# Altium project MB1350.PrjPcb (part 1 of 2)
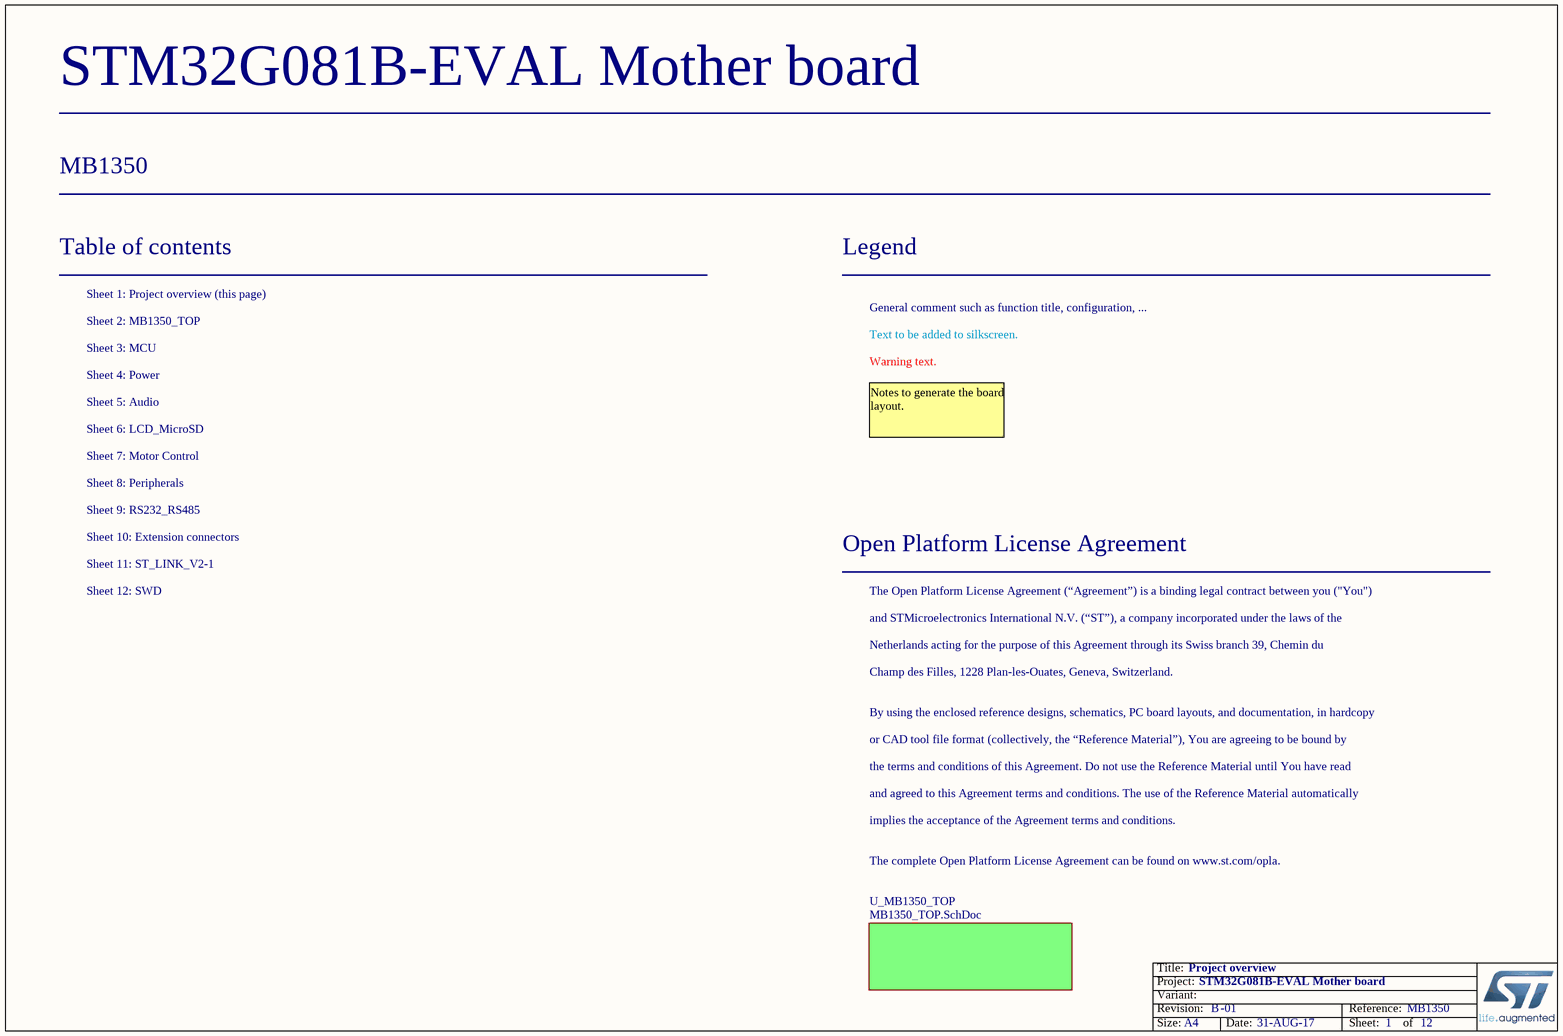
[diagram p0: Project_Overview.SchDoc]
Board_Assembly_Revision: 01; Board_Document_Date: 31-AUG-17; Board_Name: STM32G081B-EVAL Mother board; Board_PCB_Revision: B; Board_Reference: MB1350
12 sheets, 361 parts. Net scope: flat (ports and power ports of the same name join across sheets).
Sheets:
  Project_Overview.SchDoc
    U_MB1350_TOP = MB1350_TOP.SchDoc
      U_LCD_MicroSD = LCD_MicroSD.SchDoc
      U_RS232_RS485 = RS232_RS485.SchDoc
      U_ST_LINK_V2-1 = ST_LINK_V2-1.SchDoc
      U_SWD = SWD.SchDoc
      U_Peripherals = Peripherals.SchDoc
      U_MCU = MCU.SchDoc
      U_Power = Power.SchDoc
      U_Motor Control = Motor Control.SchDoc
      U_Extension connectors = Extension connectors.SchDoc
      U_Audio = Audio.SchDoc

## Sheet Project_Overview.SchDoc: Project overview
size A4; Date: Not used; ApprovedBy: Not used; CheckedBy: Not used; Author: Not used; CompanyName: STMicroelectronics; DrawnBy: Not used; Engineer: Not used; Organization: Not used; Address1: Not used; Address2: Not used; Address3: Not used; Address4: Not used; DocumentNumber: Not used; Revision: Not used; SheetNumber: 1; SheetTotal: 12

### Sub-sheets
U_MB1350_TOP = MB1350_TOP.SchDoc: no entries

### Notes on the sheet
- Table of contents
- Sheet 1: Project overview (this page)
- Legend
- General comment such as function title, configuration, ...
- Sheet 2: MB1350_TOP
- Sheet 3: MCU
- Sheet 4: Power
- Text to be added to silkscreen.
- Warning text.
- Sheet 6: LCD_MicroSD
- Sheet 5: Audio
- Notes to generate the board layout.
- Sheet 7: Motor Control
- Sheet 9: RS232_RS485
- Sheet 8: Peripherals
- Sheet 10: Extension connectors
- Sheet 11: ST_LINK_V2-1
- Open Platform License Agreement
- Sheet 12: SWD
- The Open Platform License Agreement (“Agreement”) is a binding legal contract between you ("You")
- and STMicroelectronics International N.V. (“ST”), a company incorporated under the laws of the
- Netherlands acting for the purpose of this Agreement through its Swiss branch 39, Chemin du
- Champ des Filles, 1228 Plan-les-Ouates, Geneva, Switzerland.
- By using the enclosed reference designs, schematics, PC board layouts, and documentation, in hardcopy
- or CAD tool file format (collectively, the “Reference Material”), You are agreeing to be bound by
- the terms and conditions of this Agreement. Do not use the Reference Material until You have read
- and agreed to this Agreement terms and conditions. The use of the Reference Material automatically
- implies the acceptance of the Agreement terms and conditions.
- The complete Open Platform License Agreement can be found on www.st.com/opla.

## Sheet MB1350_TOP.SchDoc: MB1350_TOP
size A4; SheetNumber: 2; SheetTotal: 12
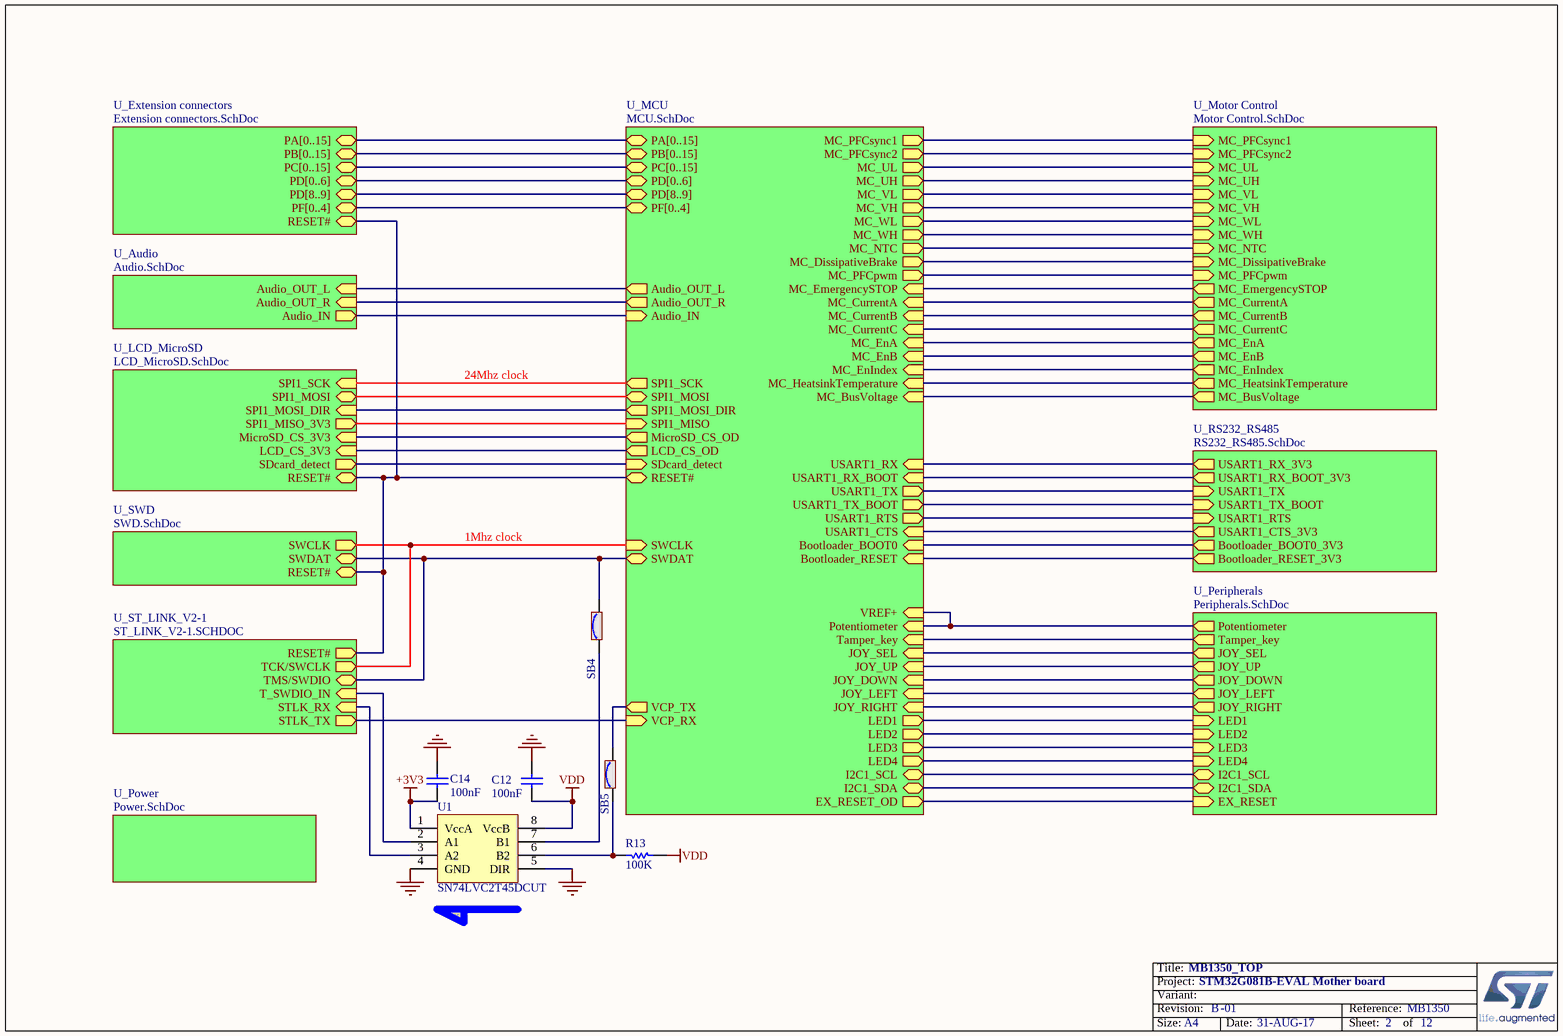
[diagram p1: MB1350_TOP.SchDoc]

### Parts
C12  100nF  [0603C]
C14  100nF  [0603C]
R13  100K  [0603R]
SB4  Solder Bridge ON  [SB_0603]  (value not drawn)
SB5  Solder Bridge ON  [SB_0603]  (value not drawn)
U1  SN74LVC2T45DCUT  [USOP8_0R5_2X3R1]

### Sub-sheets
U_Audio = Audio.SchDoc: Audio_IN (out), Audio_OUT_L (in), Audio_OUT_R (in)
U_Extension connectors = Extension connectors.SchDoc: PA[0..15] (bidir), PB[0..15] (bidir), PC[0..15] (bidir), PD[0..6] (bidir), PF[0..4] (bidir), PD[8..9] (bidir), RESET# (bidir)
U_LCD_MicroSD = LCD_MicroSD.SchDoc: MicroSD_CS_3V3 (in), LCD_CS_3V3 (in), SDcard_detect (out), RESET# (bidir), SPI1_MISO_3V3 (out), SPI1_MOSI (bidir), SPI1_MOSI_DIR (in), SPI1_SCK (in)
U_MCU = MCU.SchDoc: RESET# (bidir), LED4 (out), LED3 (out), LED1 (out), LED2 (out), Bootloader_BOOT0 (in), Bootloader_RESET (in), JOY_SEL (in), MC_BusVoltage (in), MC_CurrentA (in), Audio_OUT_L (out), Audio_OUT_R (out), SPI1_SCK (out), Potentiometer (in), SWCLK (in), USART1_TX_BOOT (out), MC_EnA (in), USART1_RX_BOOT (in), Audio_IN (in), SPI1_MOSI_DIR (out), MC_EnB (in), I2C1_SCL (bidir), I2C1_SDA (bidir), MC_EnIndex (in), MC_DissipativeBrake (out), MC_EmergencySTOP (in), SDcard_detect (in), MC_PFCsync1 (out), LCD_CS_OD (out), MicroSD_CS_OD (out), JOY_UP (in), JOY_DOWN (in), MC_HeatsinkTemperature (in), MC_CurrentC (in), MC_CurrentB (in), MC_PFCsync2 (out), MC_PFCpwm (out), Tamper_key (in), USART1_CTS (in), USART1_RTS (out), USART1_TX (out), USART1_RX (in), EX_RESET_OD (out), JOY_LEFT (in), JOY_RIGHT (in), MC_NTC (out), MC_UH (out), MC_UL (out), MC_WL (out), MC_VH (out), MC_VL (out), MC_WH (out), SPI1_MISO (in), SPI1_MOSI (bidir), SWDAT (bidir), VREF+ (in), PA[0..15] (bidir), PB[0..15] (bidir), PC[0..15] (bidir), PD[0..6] (bidir), PF[0..4] (bidir), PD[8..9] (bidir), VCP_TX (out), VCP_RX (in)
U_Motor Control = Motor Control.SchDoc: MC_EmergencySTOP (out), MC_CurrentA (out), MC_CurrentB (out), MC_CurrentC (out), MC_PFCsync1 (in), MC_PFCsync2 (in), MC_WL (in), MC_VH (in), MC_VL (in), MC_UH (in), MC_UL (in), MC_WH (in), MC_NTC (in), MC_DissipativeBrake (in), MC_PFCpwm (in), MC_EnA (out), MC_EnB (out), MC_HeatsinkTemperature (out), MC_BusVoltage (out), MC_EnIndex (out)
U_Peripherals = Peripherals.SchDoc: Potentiometer (out), LED4 (in), LED3 (in), LED1 (in), LED2 (in), Tamper_key (out), JOY_SEL (out), JOY_DOWN (out), JOY_LEFT (out), JOY_RIGHT (out), JOY_UP (out), EX_RESET (in), I2C1_SCL (bidir), I2C1_SDA (bidir)
U_Power = Power.SchDoc: no entries
U_RS232_RS485 = RS232_RS485.SchDoc: USART1_RX_3V3 (out), Bootloader_BOOT0_3V3 (out), Bootloader_RESET_3V3 (out), USART1_CTS_3V3 (out), USART1_RX_BOOT_3V3 (out), USART1_RTS (in), USART1_TX (in), USART1_TX_BOOT (in)
U_ST_LINK_V2-1 = ST_LINK_V2-1.SCHDOC: STLK_RX (in), STLK_TX (out), TMS/SWDIO (bidir), TCK/SWCLK (out), T_SWDIO_IN (in), RESET# (out)
U_SWD = SWD.SchDoc: RESET# (bidir), SWDAT (bidir), SWCLK (out)

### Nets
+3V3: C14.2 U1.1(VccA)
GND: C12.1 C14.1 U1.4(GND) U1.5(DIR)
VDD: C12.2 R13.2 U1.8(VccB)
NetR13_1: R13.1 SB5.1 U1.6(B2)
NetSB4_1: SB4.1 U1.7(B1)
NetSB4_2: SB4.2 ; sheet U_ST_LINK_V2-1/TMS/SWDIO, sheet U_SWD/SWDAT, sheet U_MCU/SWDAT
NetSB5_2: SB5.2 ; sheet U_MCU/VCP_TX
NetU1_2: U1.2(A1) ; sheet U_ST_LINK_V2-1/T_SWDIO_IN
NetU1_3: U1.3(A2) ; sheet U_ST_LINK_V2-1/STLK_RX
(unnamed): sheet U_LCD_MicroSD/MicroSD_CS_3V3, sheet U_MCU/MicroSD_CS_OD
(unnamed): sheet U_LCD_MicroSD/LCD_CS_3V3, sheet U_MCU/LCD_CS_OD  [a separate net that carries the same name]
(unnamed): sheet U_LCD_MicroSD/SDcard_detect, sheet U_MCU/SDcard_detect  [a separate net that carries the same name]
(unnamed): sheet U_LCD_MicroSD/RESET#, sheet U_ST_LINK_V2-1/RESET#, sheet U_SWD/RESET#, sheet U_MCU/RESET#, sheet U_Extension connectors/RESET#  [a separate net that carries the same name]
(unnamed): sheet U_LCD_MicroSD/SPI1_MISO_3V3, sheet U_MCU/SPI1_MISO  [a separate net that carries the same name]
(unnamed): sheet U_LCD_MicroSD/SPI1_MOSI, sheet U_MCU/SPI1_MOSI  [a separate net that carries the same name]
(unnamed): sheet U_LCD_MicroSD/SPI1_MOSI_DIR, sheet U_MCU/SPI1_MOSI_DIR  [a separate net that carries the same name]
(unnamed): sheet U_LCD_MicroSD/SPI1_SCK, sheet U_MCU/SPI1_SCK  [a separate net that carries the same name]
(unnamed): sheet U_RS232_RS485/USART1_RX_3V3, sheet U_MCU/USART1_RX  [a separate net that carries the same name]
(unnamed): sheet U_RS232_RS485/Bootloader_BOOT0_3V3, sheet U_MCU/Bootloader_BOOT0  [a separate net that carries the same name]
(unnamed): sheet U_RS232_RS485/Bootloader_RESET_3V3, sheet U_MCU/Bootloader_RESET  [a separate net that carries the same name]
(unnamed): sheet U_RS232_RS485/USART1_CTS_3V3, sheet U_MCU/USART1_CTS  [a separate net that carries the same name]
(unnamed): sheet U_RS232_RS485/USART1_RX_BOOT_3V3, sheet U_MCU/USART1_RX_BOOT  [a separate net that carries the same name]
(unnamed): sheet U_RS232_RS485/USART1_RTS, sheet U_MCU/USART1_RTS  [a separate net that carries the same name]
(unnamed): sheet U_RS232_RS485/USART1_TX, sheet U_MCU/USART1_TX  [a separate net that carries the same name]
(unnamed): sheet U_RS232_RS485/USART1_TX_BOOT, sheet U_MCU/USART1_TX_BOOT  [a separate net that carries the same name]
(unnamed): sheet U_ST_LINK_V2-1/STLK_TX, sheet U_MCU/VCP_RX  [a separate net that carries the same name]
(unnamed): sheet U_ST_LINK_V2-1/TCK/SWCLK, sheet U_SWD/SWCLK, sheet U_MCU/SWCLK  [a separate net that carries the same name]
(unnamed): sheet U_Peripherals/Potentiometer, sheet U_MCU/Potentiometer, sheet U_MCU/VREF+  [a separate net that carries the same name]
(unnamed): sheet U_Peripherals/LED4, sheet U_MCU/LED4  [a separate net that carries the same name]
(unnamed): sheet U_Peripherals/LED3, sheet U_MCU/LED3  [a separate net that carries the same name]
(unnamed): sheet U_Peripherals/LED1, sheet U_MCU/LED1  [a separate net that carries the same name]
(unnamed): sheet U_Peripherals/LED2, sheet U_MCU/LED2  [a separate net that carries the same name]
(unnamed): sheet U_Peripherals/Tamper_key, sheet U_MCU/Tamper_key  [a separate net that carries the same name]
(unnamed): sheet U_Peripherals/JOY_SEL, sheet U_MCU/JOY_SEL  [a separate net that carries the same name]
(unnamed): sheet U_Peripherals/JOY_DOWN, sheet U_MCU/JOY_DOWN  [a separate net that carries the same name]
(unnamed): sheet U_Peripherals/JOY_LEFT, sheet U_MCU/JOY_LEFT  [a separate net that carries the same name]
(unnamed): sheet U_Peripherals/JOY_RIGHT, sheet U_MCU/JOY_RIGHT  [a separate net that carries the same name]
(unnamed): sheet U_Peripherals/JOY_UP, sheet U_MCU/JOY_UP  [a separate net that carries the same name]
(unnamed): sheet U_Peripherals/EX_RESET, sheet U_MCU/EX_RESET_OD  [a separate net that carries the same name]
(unnamed): sheet U_Peripherals/I2C1_SCL, sheet U_MCU/I2C1_SCL  [a separate net that carries the same name]
(unnamed): sheet U_Peripherals/I2C1_SDA, sheet U_MCU/I2C1_SDA  [a separate net that carries the same name]
(unnamed): sheet U_MCU/MC_BusVoltage, sheet U_Motor Control/MC_BusVoltage  [a separate net that carries the same name]
(unnamed): sheet U_MCU/MC_CurrentA, sheet U_Motor Control/MC_CurrentA  [a separate net that carries the same name]
(unnamed): sheet U_MCU/Audio_OUT_L, sheet U_Audio/Audio_OUT_L  [a separate net that carries the same name]
(unnamed): sheet U_MCU/Audio_OUT_R, sheet U_Audio/Audio_OUT_R  [a separate net that carries the same name]
(unnamed): sheet U_MCU/MC_EnA, sheet U_Motor Control/MC_EnA  [a separate net that carries the same name]
(unnamed): sheet U_MCU/Audio_IN, sheet U_Audio/Audio_IN  [a separate net that carries the same name]
(unnamed): sheet U_MCU/MC_EnB, sheet U_Motor Control/MC_EnB  [a separate net that carries the same name]
(unnamed): sheet U_MCU/MC_EnIndex, sheet U_Motor Control/MC_EnIndex  [a separate net that carries the same name]
(unnamed): sheet U_MCU/MC_DissipativeBrake, sheet U_Motor Control/MC_DissipativeBrake  [a separate net that carries the same name]
(unnamed): sheet U_MCU/MC_EmergencySTOP, sheet U_Motor Control/MC_EmergencySTOP  [a separate net that carries the same name]
(unnamed): sheet U_MCU/MC_PFCsync1, sheet U_Motor Control/MC_PFCsync1  [a separate net that carries the same name]
(unnamed): sheet U_MCU/MC_HeatsinkTemperature, sheet U_Motor Control/MC_HeatsinkTemperature  [a separate net that carries the same name]
(unnamed): sheet U_MCU/MC_CurrentC, sheet U_Motor Control/MC_CurrentC  [a separate net that carries the same name]
(unnamed): sheet U_MCU/MC_CurrentB, sheet U_Motor Control/MC_CurrentB  [a separate net that carries the same name]
(unnamed): sheet U_MCU/MC_PFCsync2, sheet U_Motor Control/MC_PFCsync2  [a separate net that carries the same name]
(unnamed): sheet U_MCU/MC_PFCpwm, sheet U_Motor Control/MC_PFCpwm  [a separate net that carries the same name]
(unnamed): sheet U_MCU/MC_NTC, sheet U_Motor Control/MC_NTC  [a separate net that carries the same name]
(unnamed): sheet U_MCU/MC_UH, sheet U_Motor Control/MC_UH  [a separate net that carries the same name]
(unnamed): sheet U_MCU/MC_UL, sheet U_Motor Control/MC_UL  [a separate net that carries the same name]
(unnamed): sheet U_MCU/MC_WL, sheet U_Motor Control/MC_WL  [a separate net that carries the same name]
(unnamed): sheet U_MCU/MC_VH, sheet U_Motor Control/MC_VH  [a separate net that carries the same name]
(unnamed): sheet U_MCU/MC_VL, sheet U_Motor Control/MC_VL  [a separate net that carries the same name]
(unnamed): sheet U_MCU/MC_WH, sheet U_Motor Control/MC_WH  [a separate net that carries the same name]

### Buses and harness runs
bus sheet U_Extension connectors/PA[0..15] = sheet U_MCU/PA[0..15]
bus sheet U_Extension connectors/PB[0..15] = sheet U_MCU/PB[0..15]
bus sheet U_Extension connectors/PC[0..15] = sheet U_MCU/PC[0..15]
bus sheet U_Extension connectors/PD[0..6] = sheet U_MCU/PD[0..6]
bus sheet U_Extension connectors/PD[8..9] = sheet U_MCU/PD[8..9]
bus sheet U_Extension connectors/PF[0..4] = sheet U_MCU/PF[0..4]

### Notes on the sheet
- 24Mhz clock
- 1Mhz clock

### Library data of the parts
C12 C14 = CAP: Capacitor; Value: 100pF
R13 = Res1: Resistor; Value: 1K
SB4 SB5 = SB_ON: Fitted: YES; Ordered by: Subcon

## Sheet LCD_MicroSD.SchDoc: LCD_MicroSD
size A4; SheetNumber: 6; SheetTotal: 12
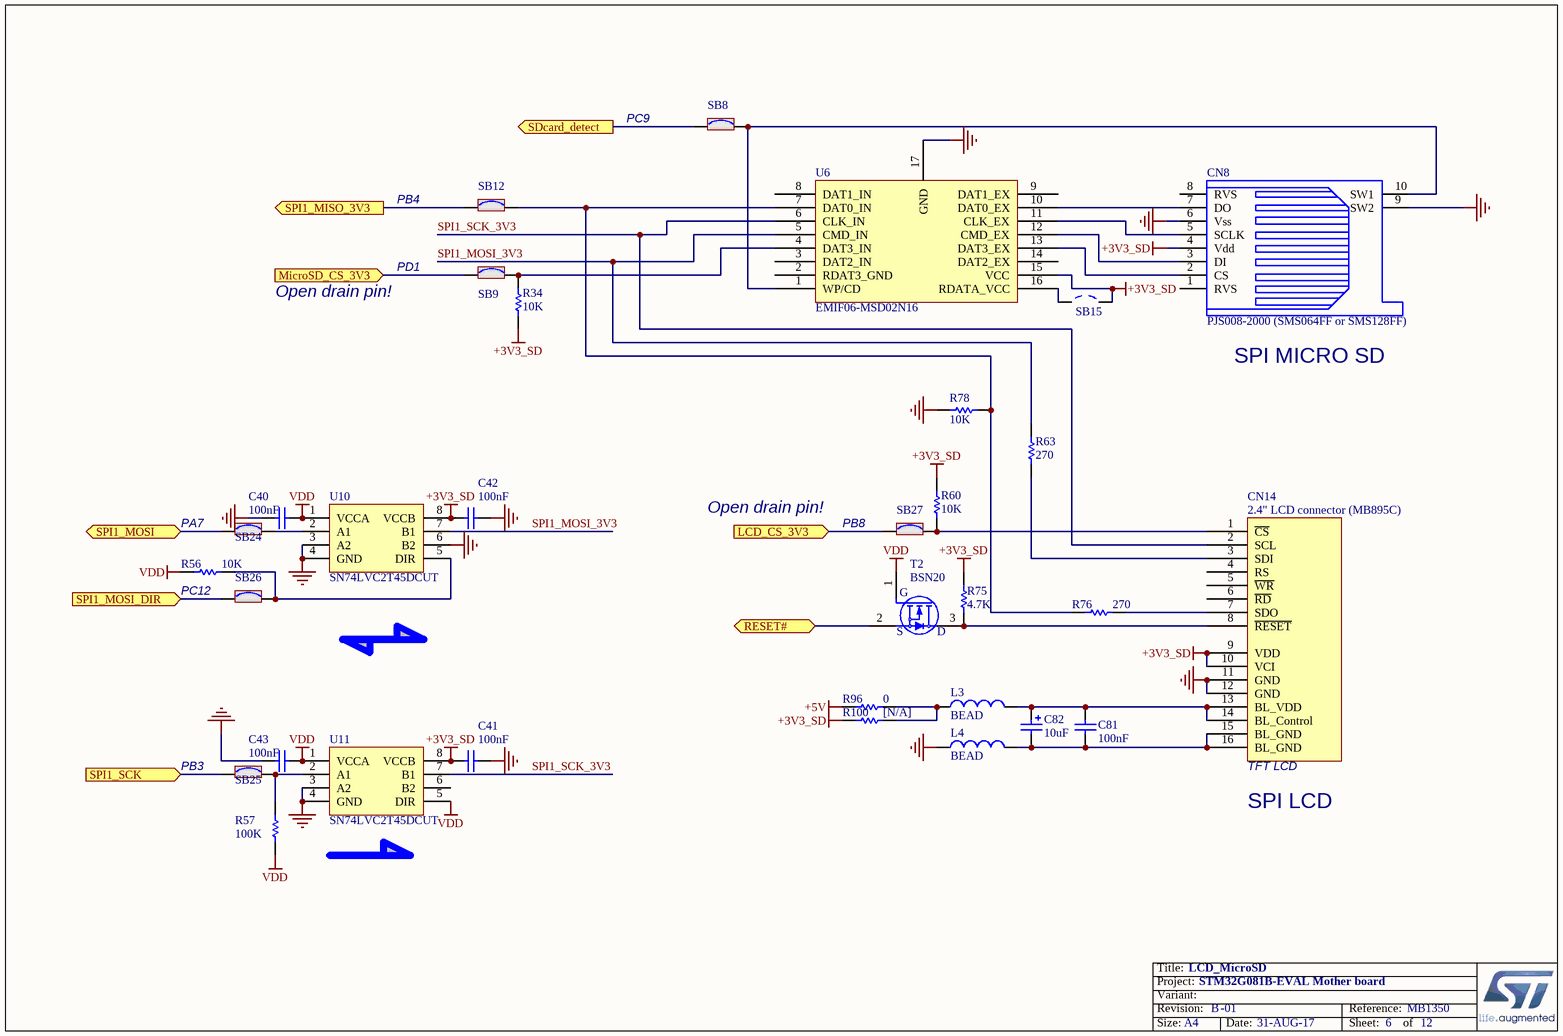
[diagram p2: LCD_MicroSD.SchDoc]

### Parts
C40  100nF  [0603C]
C41  100nF  [0603C]
C42  100nF  [0603C]
C43  100nF  [0603C]
C81  100nF  [0603C]
C82  10uF  [TAN-A]
CN8  PJS008-2000 (SMS064FF or SMS128FF)  [MSD_PJS008_]
CN14  2.4" LCD connector (MB895C)  [MB895CS]
L3  BEAD  [0603L]
L4  BEAD  [0603L]
R34  10K  [0603R]
R56  10K  [0603R]
R57  100K  [0603R]
R60  10K  [0603R]
R63  270  [0603R]
R75  4.7K  [0603R]
R76  270  [0603R]
R78  10K  [0603R]
R96  0  [0603R]
R100  [N/A]  [0603R]
SB8  Solder Bridge ON  [SB_0603]  (value not drawn)
SB9  Solder Bridge ON  [SB_0603]  (value not drawn)
SB12  Solder Bridge ON  [SB_0603]  (value not drawn)
SB15  Solder Bridge OFF  [SB_0603]  (value not drawn)
SB24  Solder Bridge ON  [SB_0603]  (value not drawn)
SB25  Solder Bridge ON  [SB_0603]  (value not drawn)
SB26  Solder Bridge ON  [SB_0603]  (value not drawn)
SB27  Solder Bridge ON  [SB_0603]  (value not drawn)
T2  BSN20  [SOT-23]
U6  EMIF06-MSD02N16  [DFN16_0R4_3R5X1R2]
U10  SN74LVC2T45DCUT  [USOP8_0R5_2X3R1]
U11  SN74LVC2T45DCUT  [USOP8_0R5_2X3R1]

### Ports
LCD_CS_3V3 (in), MicroSD_CS_3V3 (in), RESET# (bidir), SDcard_detect (out), SPI1_MISO_3V3 (out), SPI1_MOSI (bidir), SPI1_MOSI_DIR (in), SPI1_SCK (in)

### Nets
+3V3_SD: C41.2 C42.2 CN8.4(Vdd) CN14.9(VDD) CN14.10(VCI) R34.2 R60.2 R75.2 R100.1 SB15.2 U6.15(VCC) U10.8(VCCB) U11.8(VCCB)
+5V: R96.1
GND: C40.1 C41.1 C42.1 C43.1 CN8.6(Vss) CN8.9(SW2) CN14.11(GND) CN14.12(GND) L4.1 R78.1 U6.17(GND) U10.3(A2) U10.4(GND) U10.6(B2) U11.3(A2) U11.4(GND)
VDD: C40.2 C43.2 R56.2 R57.2 T2.1(G) U10.1(VCCA) U11.1(VCCA) U11.5(DIR)
LCD_CS_3V3: SB27.1 ; port LCD_CS_3V3
MicroSD_CS_3V3: SB9.1 ; port MicroSD_CS_3V3
PA7: SB24.1 ; port SPI1_MOSI
PB3: SB25.1 ; port SPI1_SCK
PC9: SB8.1 ; port SDcard_detect
PC12: SB26.1 ; port SPI1_MOSI_DIR
RESET#: T2.2(S) ; port RESET#
SPI1_MISO_3V3: SB12.1 ; port SPI1_MISO_3V3
SPI1_MOSI_3V3: R63.2 U6.5(CMD_IN) U10.7(B1)
SPI1_SCK_3V3: CN14.2(SCL) U6.6(CLK_IN) U11.7(B1)
NetC81_1: C81.1 C82.1 CN14.13(BL_VDD) CN14.14(BL_Control) L3.2
NetC81_2: C81.2 C82.2 CN14.15(BL_GND) CN14.16(BL_GND) L4.2
NetCN8_2: CN8.2(CS) U6.13(DAT3_EX)
NetCN8_3: CN8.3(DI) U6.12(CMD_EX)
NetCN8_5: CN8.5(SCLK) U6.11(CLK_EX)
NetCN8_7: CN8.7(DO) U6.10(DAT0_EX)
NetCN8_10: CN8.10(SW1) SB8.2 U6.1(WP/CD)
NetCN14_1: CN14.1(~{CS}) R60.1 SB27.2
NetCN14_3: CN14.3(SDI) R63.1
NetCN14_7: CN14.7(SDO) R76.2
NetCN14_8: CN14.8(~{RESET}) R75.1 T2.3(D)
NetL3_1: L3.1 R96.2 R100.2
NetR34_1: R34.1 SB9.2 U6.4(DAT3_IN)
NetR56_1: R56.1 SB26.2 U10.5(DIR)
NetR57_1: R57.1 SB25.2 U11.2(A1)
NetR76_1: R76.1 R78.2 SB12.2 U6.7(DAT0_IN)
NetSB15_1: SB15.1 U6.16(RDATA_VCC)
NetSB24_2: SB24.2 U10.2(A1)

Not connected (* = marked no-connect by the designer): CN8 1(RVS) 8(RVS); CN14 4(RS) 5(~{WR}) 6(~{RD}); U6 2(RDAT3_GND) 3(DAT2_IN) 8(DAT1_IN) 9(DAT1_EX) 14(DAT2_EX); U11 6(B2)

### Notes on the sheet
- PC9
- PB4
- Open drain pin!
- PD1
- SPI MICRO SD
- PA7
- (near SB27) PB8
- (near R56) PC12
- (near SB25) PB3
- (near CN14) TFT LCD
- (near CN14) SPI LCD

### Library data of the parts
C40-C43 = CAP: Capacitor; Value: 100pF
C81 = Cap: Capacitor; Value: 10nF
C82 = Cap Pol1: Polarized Capacitor (Radial)
CN8 = SMS016AFA5E
CN14 = ColorLCD_module
L3 L4 = Inductor: Value: 100uH
R34 R56 R57 R60 R63 R75 R76 R78 R96 R100 = Res1: Resistor; Value: 1K
SB8 SB9 SB12 SB24-SB27 = SB_ON: Fitted: YES; Ordered by: Subcon
SB15 = SB_OFF: Fitted: NO; Ordered by: Subcon
T2 = 2N7000

## Sheet RS232_RS485.SchDoc: RS232_RS485
size A4; SheetNumber: 9; SheetTotal: 12
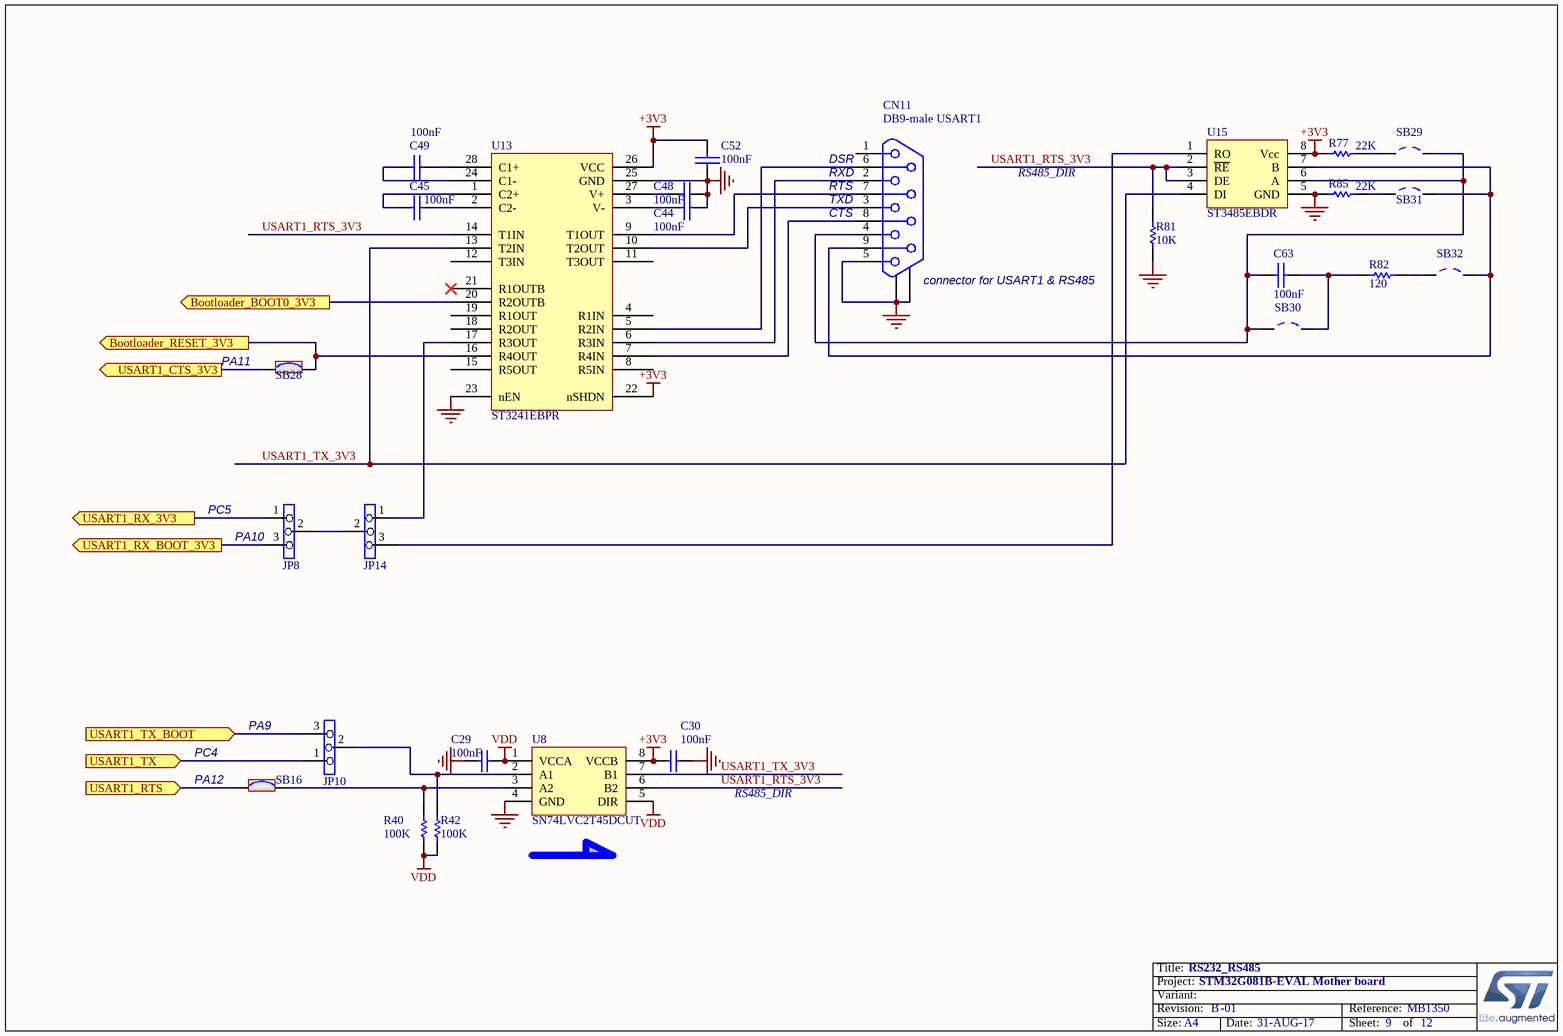
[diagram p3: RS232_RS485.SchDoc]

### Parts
C29  100nF  [0603C]
C30  100nF  [0603C]
C44  100nF  [0603C]
C45  100nF  [0603C]
C48  100nF  [0603C]
C49  100nF  [0603C]
C52  100nF  [0603C]
C63  100nF  [0603C]
CN11  DB9-male USART1  [DB9/M]
JP8  (no value)  [SIP3]
JP10  (no value)  [SIP3]
JP14  (no value)  [SIP3]
R40  100K  [0603R]
R42  100K  [0603R]
R77  22K  [0603R]
R81  10K  [0603R]
R82  120  [0603R]
R85  22K  [0603R]
SB16  Solder Bridge ON  [SB_0603]  (value not drawn)
SB28  Solder Bridge ON  [SB_0603]  (value not drawn)
SB29  Solder Bridge OFF  [SB_0603]  (value not drawn)
SB30  Solder Bridge OFF  [SB_0603]  (value not drawn)
SB31  Solder Bridge OFF  [SB_0603]  (value not drawn)
SB32  Solder Bridge OFF  [SB_0603]  (value not drawn)
U8  SN74LVC2T45DCUT  [USOP8_0R5_2X3R1]
U13  ST3241EBPR  [SSOP28_0R65_10R2X7R8]
U15  ST3485EBDR  [SOIC8_1R27_4R9X6]

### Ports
Bootloader_BOOT0_3V3 (out), Bootloader_RESET_3V3 (out), USART1_CTS_3V3 (out), USART1_RTS (in), USART1_RX_3V3 (out), USART1_RX_BOOT_3V3 (out), USART1_TX (in), USART1_TX_BOOT (in)

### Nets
+3V3: C30.2 C52.2 R77.2 U8.8(VCCB) U13.22(nSHDN) U13.26(VCC) U15.8(Vcc)
GND: C29.1 C30.1 C44.2 C48.2 C52.1 CN11.5 CN11.10 CN11.11 R81.1 R85.2 U8.4(GND) U13.23(nEN) U13.25(GND) U15.5(GND)
VDD: C29.2 R40.2 R42.2 U8.1(VCCA) U8.5(DIR)
Bootloader_BOOT0_3V3: U13.20(R2OUTB) ; port Bootloader_BOOT0_3V3
Bootloader_RESET_3V3: SB28.2 U13.16(R4OUT) ; port Bootloader_RESET_3V3
PA9: JP10.3 ; port USART1_TX_BOOT
PA12: SB16.1 ; port USART1_RTS
PC4: JP10.1 ; port USART1_TX
USART1_CTS_3V3: SB28.1 ; port USART1_CTS_3V3
USART1_RTS_3V3: R81.2 U8.6(B2) U13.14(T1IN) U15.2(~{RE}) U15.3(DE)
USART1_RX_3V3: JP8.1 ; port USART1_RX_3V3
USART1_RX_BOOT_3V3: JP8.3 ; port USART1_RX_BOOT_3V3
USART1_TX_3V3: U8.7(B1) U13.13(T2IN) U15.4(DI)
NetC44_1: C44.1 U13.3(V-)
NetC45_1: C45.1 U13.1(C2+)
NetC45_2: C45.2 U13.2(C2-)
NetC48_1: C48.1 U13.27(V+)
NetC49_1: C49.1 U13.24(C1-)
NetC49_2: C49.2 U13.28(C1+)
NetC63_1: C63.1 R82.1 SB30.2
NetC63_2: C63.2 CN11.4 SB29.2 SB30.1 U15.6(A)
NetCN11_2: CN11.2 U13.6(R3IN)
NetCN11_3: CN11.3 U13.10(T2OUT)
NetCN11_6: CN11.6 U13.5(R2IN)
NetCN11_7: CN11.7 U13.9(T1OUT)
NetCN11_8: CN11.8 U13.7(R4IN)
NetCN11_9: CN11.9 SB31.2 SB32.2 U15.7(B)
NetJP8_2: JP8.2 JP14.2
NetJP10_2: JP10.2 R42.1 U8.2(A1)
NetJP14_1: JP14.1 U13.17(R3OUT)
NetJP14_3: JP14.3 U15.1(RO)
NetR40_1: R40.1 SB16.2 U8.3(A2)
NetR77_1: R77.1 SB29.1
NetR82_2: R82.2 SB32.1
NetR85_1: R85.1 SB31.1

Not connected (* = marked no-connect by the designer): CN11 1; U13 4(R1IN) 8(R5IN) 11(T3OUT) 12(T3IN) 15(R5OUT) 18(R2OUT) 19(R1OUT) 21(R1OUTB)*

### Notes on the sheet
- (near CN11) RXD
- (near CN11) DSR
- RS485_DIR
- (near CN11) RTS
- (near CN11) TXD
- (near CN11) CTS
- (near CN11) connector for USART1 & RS485
- (near SB28) PA11
- PC5
- (near JP8) PA10
- (near SB16) PA12
- (near SB16) PC4
- PA9

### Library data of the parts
C29 C30 = CAP: Capacitor; Value: 100pF
C44 C45 C48 C49 C52 C63 = CAP: Capacitor
CN11 = DB9
JP8 JP10 JP14 = Jumper3
R40 R42 R77 R81 R82 R85 = Res1: Resistor; Value: 1K
SB16 SB28 = SB_ON: Fitted: YES; Ordered by: Subcon
SB29-SB32 = SB_OFF: Fitted: NO; Ordered by: Subcon
U13 = ST3241
U15 = ST485ABDR

## Sheet ST_LINK_V2-1.SchDoc: ST_LINK_V2-1
size A4; SheetNumber: 11; SheetTotal: 12
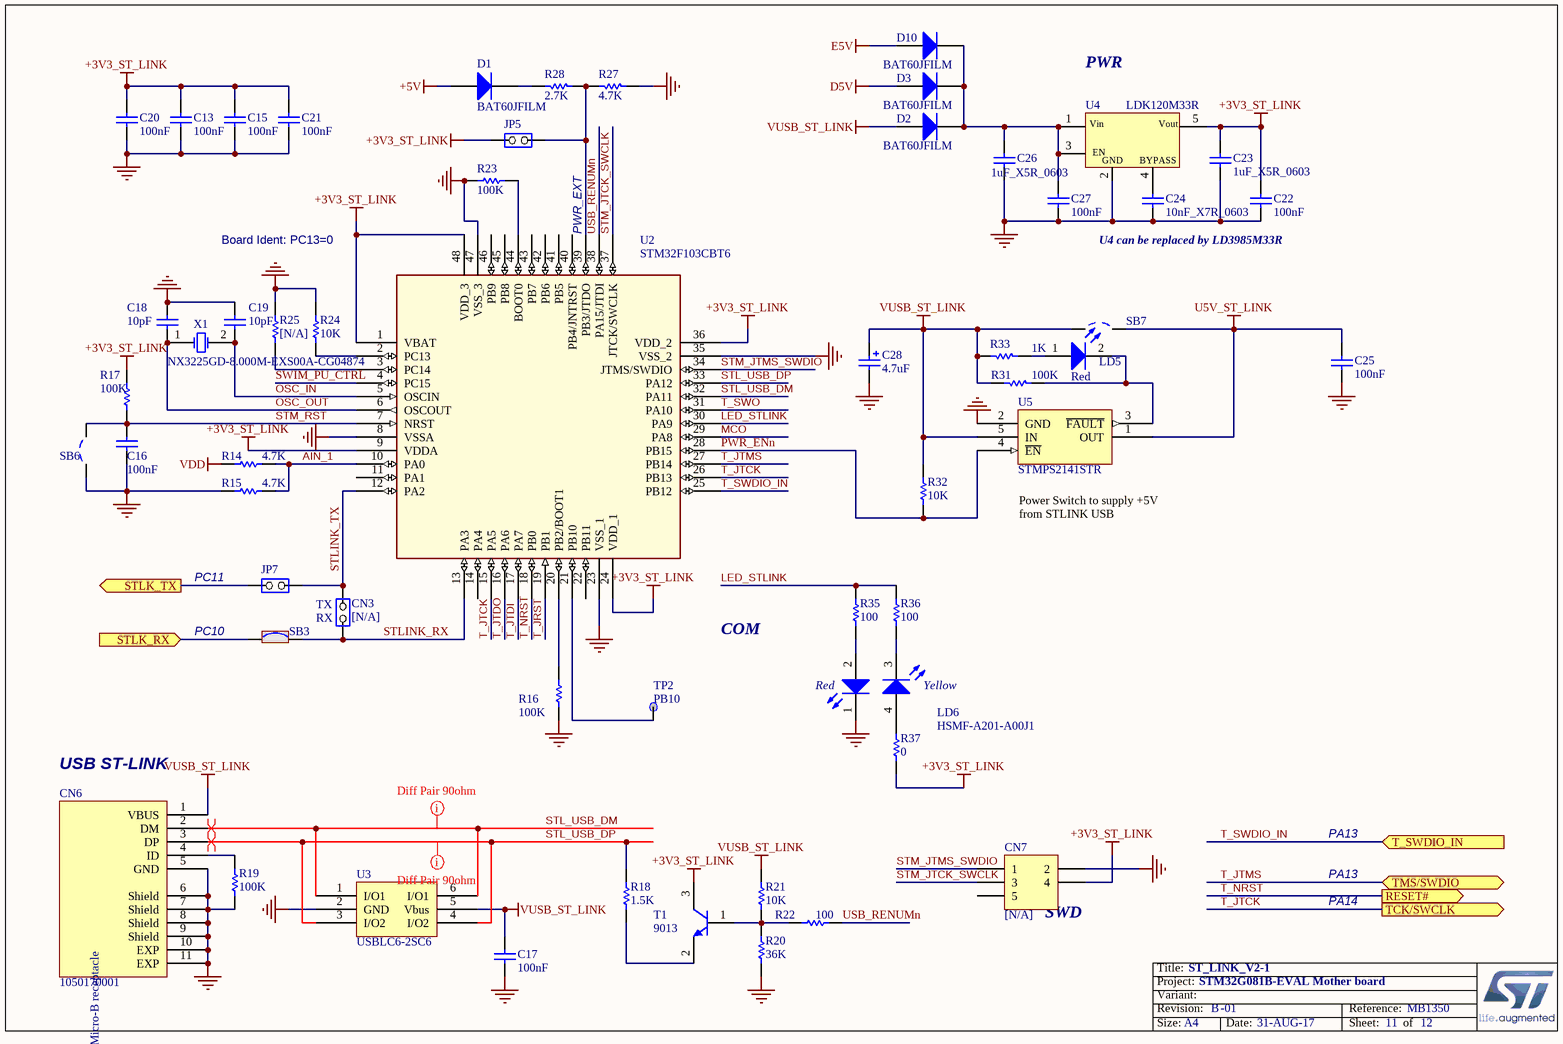
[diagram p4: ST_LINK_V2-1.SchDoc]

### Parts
C13  100nF  [0603C]
C15  100nF  [0603C]
C16  100nF  [0603C]
C17  100nF  [0603C]
C18  10pF  [0603C]
C19  10pF  [0603C]
C20  100nF  [0603C]
C21  100nF  [0603C]
C22  100nF  [0603C]
C23  1uF_X5R_0603  [0603C]
C24  10nF_X7R_0603  [0603C]
C25  100nF  [0603C]
C26  1uF_X5R_0603  [0603C]
C27  100nF  [0603C]
C28  4.7uF  [TAN-A]
CN3  [N/A]  [SIP2]
CN6  1050170001  [MICRO_USB_B_105017]
CN7  [N/A]  [HDR_2X3-1_2R54-6]
D1  BAT60JFILM  [SOD-323]
D2  BAT60JFILM  [SOD-323]
D3  BAT60JFILM  [SOD-323]
D10  BAT60JFILM  [SOD-323]
JP5  (no value)  [SIP2]
JP7  (no value)  [SIP2]
LD5  Red  [0603D]
LD6  HSMF-A201-A00J1  [LED2_3528]
R14  4.7K  [0603R]
R15  4.7K  [0603R]
R16  100K  [0603R]
R17  100K  [0603R]
R18  1.5K  [0603R]
R19  100K  [0603R]
R20  36K  [0603R]
R21  10K  [0603R]
R22  100  [0603R]
R23  100K  [0603R]
R24  10K  [0603R]
R25  [N/A]  [0603R]
R27  4.7K  [0603R]
R28  2.7K  [0603R]
R31  100K  [0603R]
R32  10K  [0603R]
R33  1K  [0603R]
R35  100  [0603R]
R36  100  [0603R]
R37  0  [0603R]
SB3  Solder Bridge ON  [SB_0603]  (value not drawn)
SB6  Solder Bridge OFF  [SB_0603]  (value not drawn)
SB7  Solder Bridge OFF  [SB_0603]  (value not drawn)
T1  9013  [SOT-23]
TP2  PB10  [TP]
U2  STM32F103CBT6  [LQFP48_0R5_9X9]
U3  USBLC6-2SC6  [SOT23-6L]
U4  LDK120M33R  [SOT23-5]
U5  STMPS2141STR  [MOS_SOT23-5L]
X1  NX3225GD-8.000M-EXS00A-CG04874  [XTAL_2SM_3R2X2R5_H1]

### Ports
RESET# (out), STLK_RX (in), STLK_TX (out), T_SWDIO_IN (in), TCK/SWCLK (out), TMS/SWDIO (bidir)

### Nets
+3V3_ST_LINK: C13.2 C15.2 C20.2 C21.2 C22.2 C23.1 CN7.4 JP5.1(COMMON) R17.2 R37.2 T1.3(C) U2.1(VBAT) U2.9(VDDA) U2.24(VDD_1) U2.36(VDD_2) U2.48(VDD_3) U4.5(Vout)
+5V: D1.1(A)
D5V: D3.1(A)
E5V: D10.1(A)
GND: C13.1 C15.1 C16.1 C17.1 C18.2 C19.2 C20.1 C21.1 C22.1 C23.2 C24.1 C25.1 C26.1 C27.1 C28.2 CN6.5(GND) CN6.6(Shield) CN6.7(Shield) CN6.8(Shield) CN6.9(Shield) CN6.10(EXP) CN6.11(EXP) CN7.2 LD6.1(RED_cathode) R15.1 R16.1 R19.2 R20.1 R23.1 R24.1 R25.1 R27.2 SB6.1 U2.8(VSSA) U2.23(VSS_1) U2.35(VSS_2) U2.47(VSS_3) U3.2(GND) U4.2(GND) U5.2(GND)
U5V_ST_LINK: C25.2 SB7.2 U5.1(OUT)
VDD: R14.1
VUSB_ST_LINK: C17.2 C28.1 CN6.1(VBUS) D2.1(A) R21.2 R31.1 R32.1 R33.1 SB7.1 U3.5(Vbus) U5.5(IN)
AIN_1: R14.2 R15.2 U2.10(PA0)
LED_STLINK: R35.1 R36.1 U2.30(PA9)
MCO: U2.29(PA8)
OSC_IN: C19.1 U2.5(OSCIN) X1.2(OSC2)
OSC_OUT: C18.1 U2.6(OSCOUT) X1.1(OSC1)
PWR_ENn: R32.2 U2.28(PB15) U5.4(~{EN})
STL_USB_DM: CN6.2(DM) U2.32(PA11) U3.1(I/O1) U3.6(I/O1)
STL_USB_DP: CN6.3(DP) R18.1 U2.33(PA12) U3.3(I/O2) U3.4(I/O2)
STLINK_RX: CN3.1(COMMON) SB3.2 U2.13(PA3)
STLINK_TX: CN3.2(NO) JP7.2(NO) U2.12(PA2)
STLK_RX: SB3.1 ; port STLK_RX
STLK_TX: JP7.1(COMMON) ; port STLK_TX
STM_JTCK_SWCLK: CN7.3 U2.37(JTCK/SWCLK)
STM_JTMS_SWDIO: CN7.1 U2.34(JTMS/SWDIO)
STM_RST: C16.2 R17.1 SB6.2 U2.7(NRST)
SWIM_PU_CTRL: U2.4(PC15)
T_JRST: U2.19(PB1)
T_JTCK: U2.15(PA5) U2.26(PB13) ; port TCK/SWCLK
T_JTDI: U2.17(PA7)
T_JTDO: U2.16(PA6)
T_JTMS: U2.27(PB14) ; port TMS/SWDIO
T_NRST: U2.18(PB0) ; port RESET#  [project net RESET#]
T_SWDIO_IN: U2.25(PB12) ; port T_SWDIO_IN
T_SWO: U2.31(PA10)
USB_RENUMn: R22.2 U2.38(PA15/JTDI)
NetC24_2: C24.2 U4.4(BYPASS)
NetC26_2: C26.2 C27.2 D2.2(K) D3.2(K) D10.2(K) U4.1(Vin) U4.3(CE)
NetCN6_4: CN6.4(ID) R19.1
NetD1_2: D1.2(K) R28.1
NetJP5_2: JP5.2(NO) R27.1 R28.2 U2.39(PB3/JTDO)
NetLD5_1: LD5.1(A) R33.2
NetLD5_2: LD5.2(K) R31.2 U5.3(~{FAULT})
NetLD6_2: LD6.2(Red_anode) R35.2
NetLD6_3: LD6.3(YellowGreen_cathode) R36.2
NetLD6_4: LD6.4(YellowGreen_anode) R37.1
NetR16_2: R16.2 U2.20(PB2/BOOT1)
NetR18_2: R18.2 T1.2(E)
NetR20_2: R20.2 R21.1 R22.1 T1.1(B)
NetR23_2: R23.2 U2.44(BOOT0)
NetR24_2: R24.2 U2.2(PC13)
NetR25_2: R25.2 U2.3(PC14)
NetTP2_1: TP2.1 U2.21(PB10)

Not connected (* = marked no-connect by the designer): CN7 5; U2 11(PA1) 14(PA4) 22(PB11) 40(PB4/JNTRST) 41(PB5) 42(PB6) 43(PB7) 45(PB8) 46(PB9)

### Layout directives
differential pair: (no net found under the mark)
mark named Diff Pair 90ohm: STL_USB_DM, STL_USB_DP

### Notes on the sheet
- PWR
- Board Ident: PC13=0
- (near U2) PWR_EXT
- U4 can be replaced by LD3985M33R
- PC11
- (near U5) Power Switch to supply +5V from STLINK USB
- PC10
- (near CN3) TX
- (near CN3) RX
- COM
- (near CN6) USB ST-LINK
- PA13
- (near CN7) SWD
- PA14

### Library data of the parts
C13 C15-C17 C20-C22 C25 C27 = Capacitor_ST: Capacitor 0402 / 0603 / 0805
C18 C19 = Capacitor_ST: Capacitor 0402 / 0603 / 0805; Value: 100nF
C23 C26 = CAP SMD 0603  X5R 1µF 25V 10%: 0603  X5R 1µF; Rated voltage: 25V; Tolerance: 10%
C24 = CAP SMD 0603  X7R 10000PF 50V 10%: 0603  X7R 10NF; Order code RS: 2040779; Rated voltage: 50V; Tolerance: 10%
C28 = Cap Pol1: Polarized Capacitor (Radial); Value: 100pF; Ordered by: Subcon
CN3 = JP2: Fitted: NO
CN6 = 1050170001: Silkscreen: USB
CN7 = Header 3X2: Header, 3-Pin, Dual row
D1 = Diode: Default Diode; Code - JEDEC: DO-214-AB; Ordered by: STM; ECCN_US/EU: EAR99/NEC
D2 D3 D10 = BAT60JFILM: Manuf_1: STM; Provided: ST; ECCN_US/EU: EAR99/NEC
JP5 JP7 = JP2: Ordered by: Subcon; Silkscreen: Pwr_ext
LD5 = LED2: Typical RED, GREEN, YELLOW, AMBER GaAs LED
R14 R15 R25 = Resistor_ST: Resistor 0402 / 0603 / 0805; Value: 10K; Fitted: NO
R16-R19 R22 R23 = Resistor_ST: Resistor 0402 / 0603 / 0805; Value: 10K
R20 R21 R27 R28 R35-R37 = Res1: Resistor; Value: 1K
R24 R32 = Resistor_ST: Resistor 0402 / 0603 / 0805
R31 = Res1: Resistor; Value: 1K; Ordered by: Subcon
R33 = Res1: Resistor; Ordered by: Subcon
SB3 = SB_ON: Fitted: YES; Ordered by: Subcon
SB6 SB7 = SB_OFF: Fitted: NO; Ordered by: Subcon
T1 = NPN: NPN Bipolar Transistor; Code - JEDEC: TO-226-AA
TP2 = TP
U2 = STM32F103CBT6: Medium-density performance line ARM-based 32-bit MCU with 64KB Flash; Manuf_Part_1: STM32F103C8T6; Manuf_1: STM; Ref St: 9175981; Provided: ST; ECCN_US/EU: 3A991A2/NEC
U4 = LDK120M33R: 200 mA low quiescent current very low noise LDO; Manuf_1: STM; Manuf_Part_1: LD3985M33R; Provided: ST; Ref St: 9176161; ECCN_US/EU: EAR99/NEC
U5 = MCD-00083: Enhanced single channel power switches; Part_Type: IC; Manufacturer: STMICROELECTRONICS; ECCN_US: EAR99; ECCN_EU: NEC; Provided_By: Subcon; Initial_Board_Reference: MB1274
X1 = XTAL: Crystal Oscillator

## Sheet SWD.SchDoc: SWD
size A4; SheetNumber: 12; SheetTotal: 12
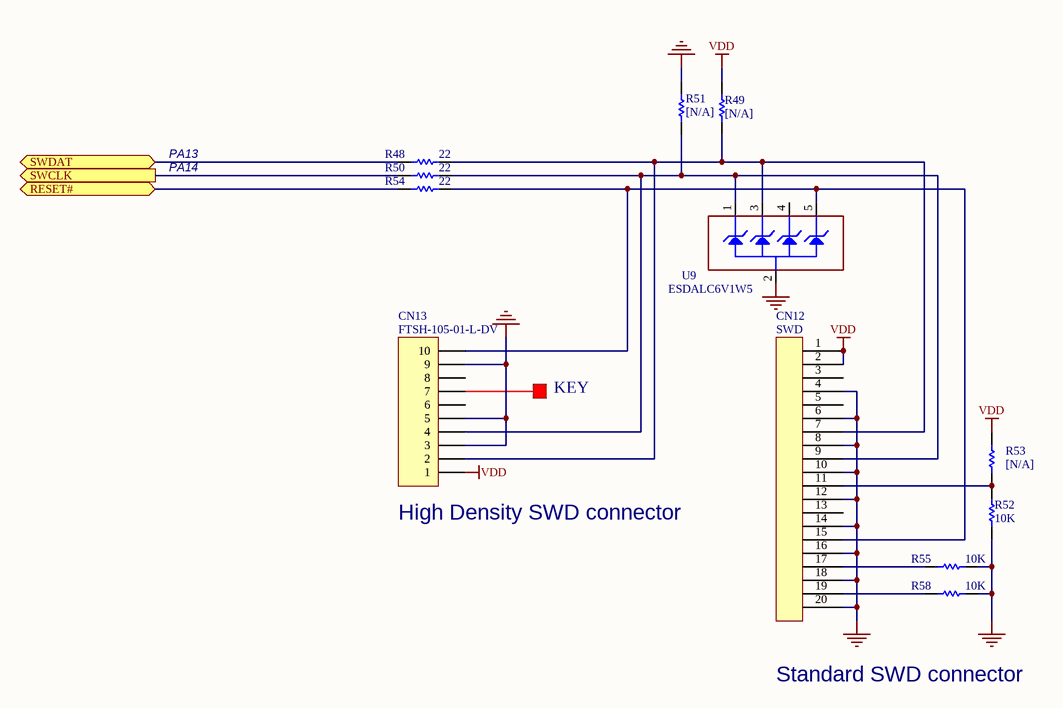
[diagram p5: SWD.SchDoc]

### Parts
CN12  SWD  [IDC20S]
CN13  FTSH-105-01-L-DV  [FTSH-105-01-L-DV]
R48  22  [0603R]
R49  [N/A]  [0603R]
R50  22  [0603R]
R51  [N/A]  [0603R]
R52  10K  [0603R]
R53  [N/A]  [0603R]
R54  22  [0603R]
R55  10K  [0603R]
R58  10K  [0603R]
U9  ESDALC6V1W5  [SC70-5]

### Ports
RESET# (bidir), SWCLK (out), SWDAT (bidir)

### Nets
GND: CN12.4 CN12.6 CN12.8 CN12.10 CN12.12 CN12.14 CN12.16 CN12.18 CN12.20 CN13.3 CN13.5 CN13.9 R51.1 R52.1 R55.1 R58.1 U9.2(GND)
VDD: CN12.1 CN12.2 CN13.1 R49.2 R53.2
PA13: R48.2 ; port SWDAT
RESET#: R54.2 ; port RESET#
SWCLK: R50.2 ; port SWCLK
NetCN12_7: CN12.7 CN13.2 R48.1 R49.1 U9.3(IO2)
NetCN12_9: CN12.9 CN13.4 R50.1 R51.2 U9.1(IO1)
NetCN12_11: CN12.11 R52.2 R53.1
NetCN12_15: CN12.15 CN13.10 R54.1 U9.5(IO4)
NetCN12_17: CN12.17 R55.2
NetCN12_19: CN12.19 R58.2

Not connected (* = marked no-connect by the designer): CN12 3 5 13; CN13 6 7 8; U9 4(IO3)

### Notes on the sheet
- PA13
- PA14
- KEY
- (near CN13) High Density SWD connector
- Standard SWD connector

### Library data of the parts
CN12 = 20PIN1
CN13 = Header 10: Header, 10-Pin
R48-R55 R58 = Res1: Resistor; Value: 1K
U9 = ESDALC6V1W5: Dual Transil array for ESD protection; Manuf_1: STM; Manuf_Part_1: ESDA6V1SC5; Ref St: 9179034; Provided: ST; ECCN_US/EU: EAR99/NEC

## Sheet Peripherals.SchDoc: Peripherals
size A4; SheetNumber: 8; SheetTotal: 12
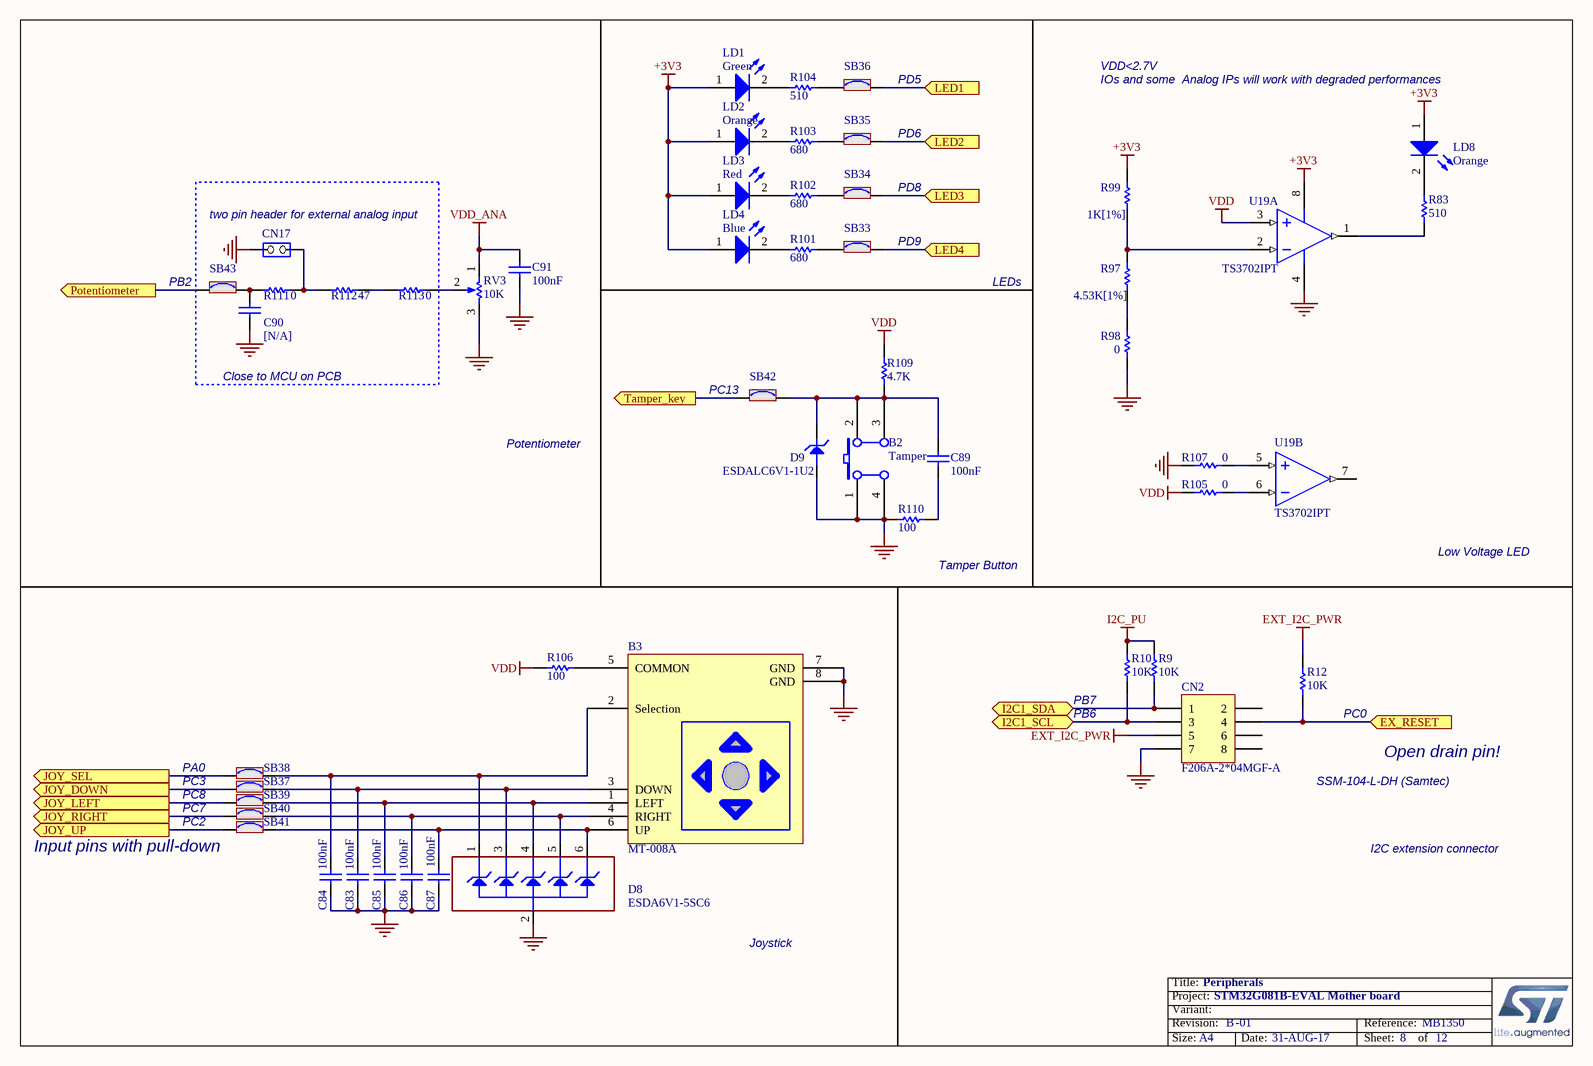
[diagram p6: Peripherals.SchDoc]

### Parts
B2  Tamper  [PB10]
B3  MT-008A  [MT-008A]
C83  100nF  [0603C]
C84  100nF  [0603C]
C85  100nF  [0603C]
C86  100nF  [0603C]
C87  100nF  [0603C]
C89  100nF  [0603C]
C90  [N/A]  [0603C]
C91  100nF  [0603C]
CN2  F206A-2*04MGF-A  [SSM-104-L-DH]
CN17  (no value)  [SIP2]
D8  ESDA6V1-5SC6  [SOT23-6L]
D9  ESDALC6V1-1U2  [D0201_21]
LD1  Green  [0603D]
LD2  Orange  [0603D]
LD3  Red  [0603D]
LD4  Blue  [0603D]
LD8  Orange  [0603D]
R9  10K  [0603R]
R10  10K  [0603R]
R12  10K  [0603R]
R83  510  [0603R]
R97  4.53K[1%]  [0603R]
R98  0  [0603R]
R99  1K[1%]  [0603R]
R101  680  [0603R]
R102  680  [0603R]
R103  680  [0603R]
R104  510  [0603R]
R105  0  [0603R]
R106  100  [0603R]
R107  0  [0603R]
R109  4.7K  [0603R]
R110  100  [0603R]
R111  0  [0603R]
R112  47  [0603R]
R113  0  [0603R]
RV3  10K  [3386P]
SB33  Solder Bridge ON  [SB_0603]  (value not drawn)
SB34  Solder Bridge ON  [SB_0603]  (value not drawn)
SB35  Solder Bridge ON  [SB_0603]  (value not drawn)
SB36  Solder Bridge ON  [SB_0603]  (value not drawn)
SB37  Solder Bridge ON  [SB_0603]  (value not drawn)
SB38  Solder Bridge ON  [SB_0603]  (value not drawn)
SB39  Solder Bridge ON  [SB_0603]  (value not drawn)
SB40  Solder Bridge ON  [SB_0603]  (value not drawn)
SB41  Solder Bridge ON  [SB_0603]  (value not drawn)
SB42  Solder Bridge ON  [SB_0603]  (value not drawn)
SB43  Solder Bridge ON  [SB_0603]  (value not drawn)
U19  TS3702IPT  [TSSOP8_0R65_3X6R4]  (parts A,B of 2)

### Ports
EX_RESET (in), I2C1_SCL (bidir), I2C1_SDA (bidir), JOY_DOWN (out), JOY_LEFT (out), JOY_RIGHT (out), JOY_SEL (out), JOY_UP (out), LED1 (in), LED2 (in), LED3 (in), LED4 (in), Potentiometer (out), Tamper_key (out)

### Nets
+3V3: LD1.1(A) LD2.1(A) LD3.1(A) LD4.1(A) LD8.1(A) R99.2 U19.8(V+)
EXT_I2C_PWR: CN2.5 R12.2
GND: B2.1(A0) B2.4(A1) B3.7(GND) B3.8(GND) C83.1 C84.1 C85.1 C86.1 C87.1 C90.1 C91.1 CN2.7 CN17.2(NO) D8.2(GND) D9.2 R98.2 R107.1 R110.1 RV3.3(TOP) U19.4(V-)
I2C_PU: R9.2 R10.2
VDD: R105.1 R106.1 R109.2 U19.3(IN+)
VDD_ANA: C91.2 RV3.1(BOT)
EX_RESET: CN2.4 R12.1 ; port EX_RESET
PA0: SB38.1 ; port JOY_SEL
PB2: SB43.1 ; port Potentiometer
PB6: CN2.3 R10.1 ; port I2C1_SCL
PB7: CN2.1 R9.1 ; port I2C1_SDA
PC2: SB41.1 ; port JOY_UP
PC3: SB37.1 ; port JOY_DOWN
PC7: SB40.1 ; port JOY_RIGHT
PC8: SB39.1 ; port JOY_LEFT
PC13: SB42.1 ; port Tamper_key
PD5: SB36.2 ; port LED1
PD6: SB35.2 ; port LED2
PD8: SB34.2 ; port LED3
PD9: SB33.2 ; port LED4
NetB2_2: B2.2(B0) B2.3(B1) C89.2 D9.1 R109.1 SB42.2
NetB3_1: B3.1(LEFT) C85.2 D8.4(IO3) SB39.2
NetB3_2: B3.2(Selection) C84.2 D8.1(IO1) SB38.2
NetB3_3: B3.3(DOWN) C83.2 D8.3(IO2) SB37.2
NetB3_4: B3.4(RIGHT) C86.2 D8.5(IO4) SB40.2
NetB3_5: B3.5(COMMON) R106.2
NetB3_6: B3.6(UP) C87.2 D8.6(IO5) SB41.2
NetC89_1: C89.1 R110.2
NetC90_2: C90.2 R111.1 SB43.2
NetCN17_1: CN17.1(COMMON) R111.2 R112.1
NetLD1_2: LD1.2(K) R104.2
NetLD2_2: LD2.2(K) R103.2
NetLD3_2: LD3.2(K) R102.2
NetLD4_2: LD4.2(K) R101.2
NetLD8_2: LD8.2(K) R83.1
NetR83_2: R83.2 U19.1(OUT)
NetR97_1: R97.1 R98.1
NetR97_2: R97.2 R99.1 U19.2(IN-)
NetR101_1: R101.1 SB33.1
NetR102_1: R102.1 SB34.1
NetR103_1: R103.1 SB35.1
NetR104_1: R104.1 SB36.1
NetR105_2: R105.2 U19.6(IN-)
NetR107_2: R107.2 U19.5(IN+)
NetR112_2: R112.2 R113.1
NetR113_2: R113.2 RV3.2(TAP)

Not connected (* = marked no-connect by the designer): CN2 2 6 8; U19 7(OUT)

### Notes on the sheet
- (near SB36) PD5
- VDD<2.7V
- IOs and some  Analog IPs will work with degraded performances
- (near SB35) PD6
- (near SB34) PD8
- (near CN17) two pin header for external analog input
- (near SB33) PD9
- (near SB43) PB2
- LEDs
- Close to MCU on PCB
- (near SB42) PC13
- Potentiometer
- (near R110) Tamper Button
- Low Voltage LED
- (near R10) PB7
- PB6
- (near R12) PC0
- PC8
- PC3
- PA0
- (near CN2) SSM-104-L-DH (Samtec)
- Open drain pin!
- (near SB41) Input pins with pull-down
- PC2
- PC7
- I2C extension connector
- Joystick

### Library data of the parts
B2 = SW PUSHBUTTON: SE PUSHBUTTON
C83-C87 C89 C91 = CAP: Capacitor; Value: 100pF
C90 = cap: Capacitor; Value: 100pF
CN2 = SSM-104-L-DH: Header, 5-Pin, Dual row
CN17 = JP2
D8 = ESDA6V1-5SC6: 5-line ESD protection; Manuf_1: STM; Provided: ST; ECCN_US/EU: EAR99/NEC
LD1-LD4 LD8 = LED2: as LD5 on sheet ST_LINK_V2-1
R9 R10 R12 R83 R97-R99 R101-R107 R110-R113 = Res1: Resistor; Value: 1K
R109 = res1: Resistor; Value: 1K
RV3 = RV
SB33-SB43 = SB_ON: Fitted: YES; Ordered by: Subcon
U19 = LM393PT

## Sheet MCU.SchDoc: MCU
size A4; SheetNumber: 3; SheetTotal: 12
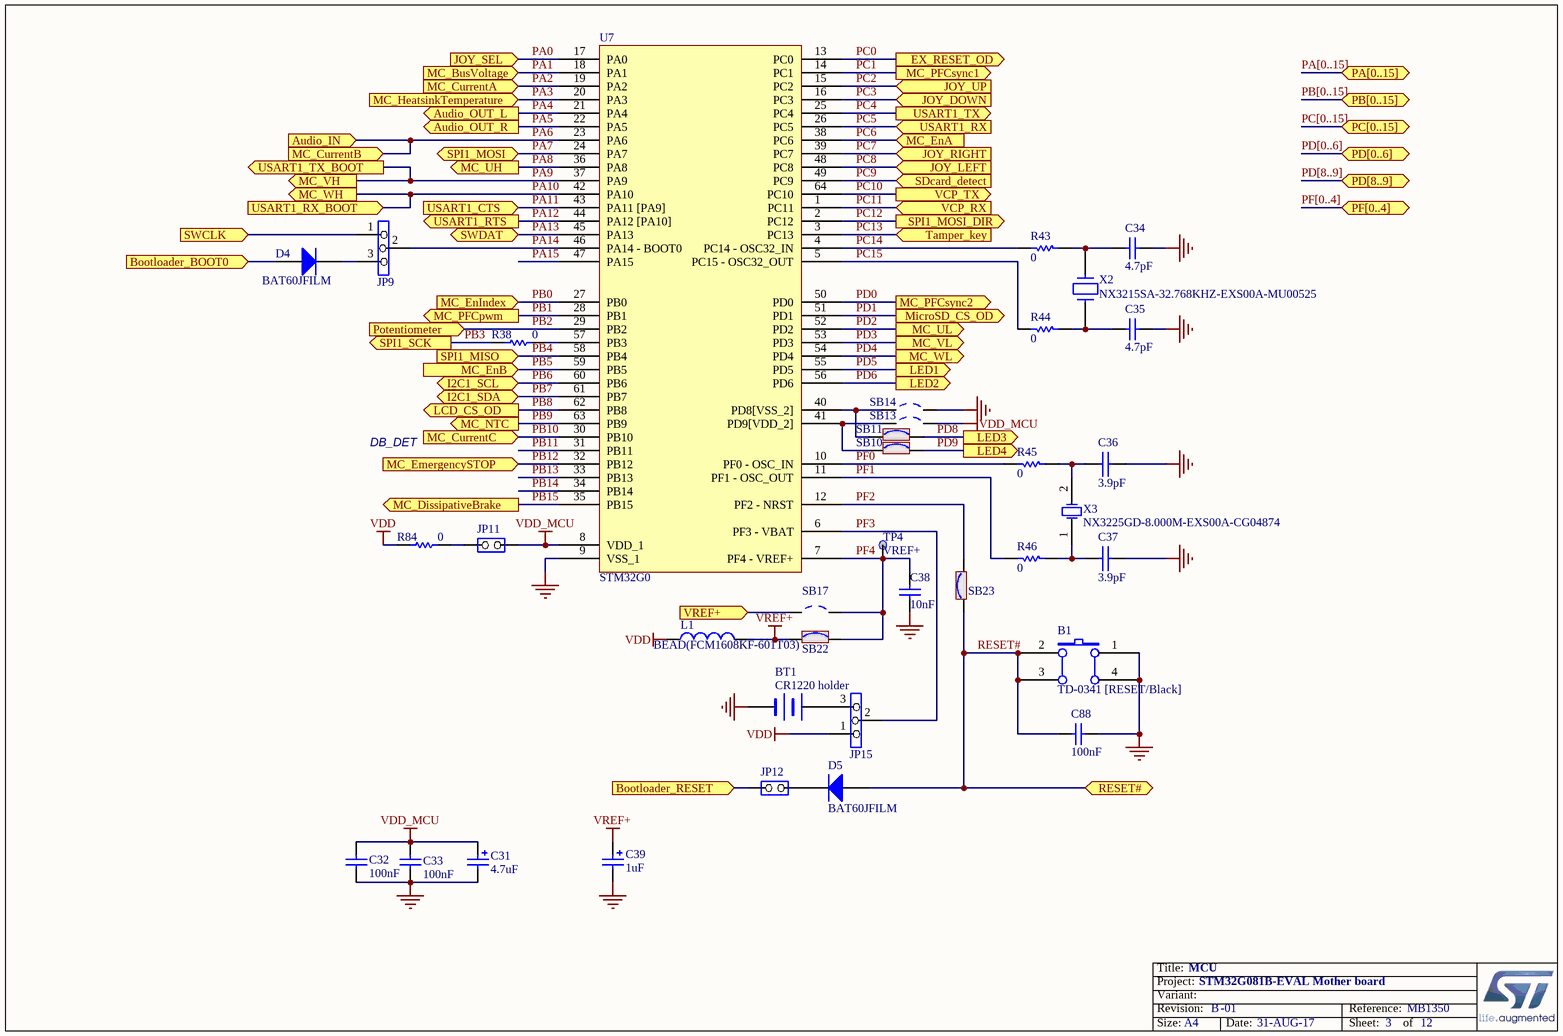
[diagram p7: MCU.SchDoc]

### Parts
B1  TD-0341 [RESET/Black]  [PB10]
BT1  CR1220 holder  [BAT_2SM_CR1220]
C31  4.7uF  [TAN-A]
C32  100nF  [0603C]
C33  100nF  [0603C]
C34  4.7pF  [0603C]
C35  4.7pF  [0603C]
C36  3.9pF  [0603C]
C37  3.9pF  [0603C]
C38  10nF  [0603C]
C39  1uF  [TAN-A]
C88  100nF  [0603C]
D4  BAT60JFILM  [SOD-323]
D5  BAT60JFILM  [SOD-323]
JP9  (no value)  [SIP3]
JP11  (no value)  [SIP2]
JP12  (no value)  [SIP2]
JP15  (no value)  [SIP3]
L1  BEAD(FCM1608KF-601T03)  [0603L]
R38  0  [0603R]
R43  0  [0603R]
R44  0  [0603R]
R45  0  [0603R]
R46  0  [0603R]
R84  0  [0603R]
SB10  Solder Bridge ON  [SB_0603]  (value not drawn)
SB11  Solder Bridge ON  [SB_0603]  (value not drawn)
SB13  Solder Bridge OFF  [SB_0603]  (value not drawn)
SB14  Solder Bridge OFF  [SB_0603]  (value not drawn)
SB17  Solder Bridge OFF  [SB_0603]  (value not drawn)
SB22  Solder Bridge ON  [SB_0603]  (value not drawn)
SB23  Solder Bridge ON  [SB_0603]  (value not drawn)
TP4  VREF+  [TP]
U7  STM32G0  [QFP64_0R5_12X12_SKT]
X2  NX3215SA-32.768KHZ-EXS00A-MU00525  [XTAL_2SM_3R2X1R5]
X3  NX3225GD-8.000M-EXS00A-CG04874  [XTAL_2SM_3R2X2R5_H1]

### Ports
Audio_IN (in), Audio_OUT_L (out), Audio_OUT_R (out), Bootloader_BOOT0 (in), Bootloader_RESET (in), EX_RESET_OD (out), I2C1_SCL (bidir), I2C1_SDA (bidir), JOY_DOWN (in), JOY_LEFT (in), JOY_RIGHT (in), JOY_SEL (in), JOY_UP (in), LCD_CS_OD (out), LED1 (out), LED2 (out), LED3 (out), LED4 (out), MC_BusVoltage (in), MC_CurrentA (in), MC_CurrentB (in), MC_CurrentC (in), MC_DissipativeBrake (out), MC_EmergencySTOP (in), MC_EnA (in), MC_EnB (in), MC_EnIndex (in), MC_HeatsinkTemperature (in), MC_NTC (out), MC_PFCpwm (out), MC_PFCsync1 (out), MC_PFCsync2 (out), MC_UH (out), MC_UL (out), MC_VH (out), MC_VL (out), MC_WH (out), MC_WL (out), MicroSD_CS_OD (out), PA[0..15] (bidir), PB[0..15] (bidir), PC[0..15] (bidir), PD[0..6] (bidir), PD[8..9] (bidir), PF[0..4] (bidir), Potentiometer (in), RESET# (bidir), SDcard_detect (in), SPI1_MISO (in), SPI1_MOSI (bidir), SPI1_MOSI_DIR (out), SPI1_SCK (out), SWCLK (in), SWDAT (bidir), Tamper_key (in), USART1_CTS (in), USART1_RTS (out), USART1_RX (in), USART1_RX_BOOT (in), USART1_TX (out), USART1_TX_BOOT (out), VCP_RX (in), VCP_TX (out), VREF+ (in)

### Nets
GND: B1.1(A0) B1.4(A1) BT1.2(-) C31.2 C32.1 C33.2 C34.2 C35.2 C36.2 C37.2 C38.1 C39.2 C88.1 SB14.2 U7.9(VSS_1)
VDD: JP15.1 L1.1 R84.2
VDD_MCU: C31.1 C32.2 C33.1 JP11.1(COMMON) SB13.2 U7.8(VDD_1)
VREF+: C39.1 L1.2 SB22.1
Bootloader_BOOT0: D4.1(A) ; port Bootloader_BOOT0
Bootloader_RESET: JP12.2(NO) ; port Bootloader_RESET
PA0: U7.17(PA0) ; port JOY_SEL
PA1: U7.18(PA1) ; port MC_BusVoltage
PA2: U7.19(PA2) ; port MC_CurrentA
PA3: U7.20(PA3) ; port MC_HeatsinkTemperature
PA4: U7.21(PA4) ; port Audio_OUT_L
PA5: U7.22(PA5) ; port Audio_OUT_R
PA6: U7.23(PA6) ; port Audio_IN, port MC_CurrentB
PA7: U7.24(PA7) ; port SPI1_MOSI
PA8: U7.36(PA8) ; port MC_UH
PA9: U7.37(PA9) ; port USART1_TX_BOOT, port MC_VH
PA10: U7.42(PA10) ; port USART1_RX_BOOT, port MC_WH
PA11: U7.43(PA11_[PA9]) ; port USART1_CTS
PA12: U7.44(PA12_[PA10]) ; port USART1_RTS
PA13: U7.45(PA13) ; port SWDAT
PA14: JP9.2 U7.46(PA14_-_BOOT0)
PA15: U7.47(PA15)
PB0: U7.27(PB0) ; port MC_EnIndex
PB1: U7.28(PB1) ; port MC_PFCpwm
PB2: U7.29(PB2) ; port Potentiometer
PB3: R38.2 ; port SPI1_SCK
PB4: U7.58(PB4) ; port SPI1_MISO
PB5: U7.59(PB5) ; port MC_EnB
PB6: U7.60(PB6) ; port I2C1_SCL
PB7: U7.61(PB7) ; port I2C1_SDA
PB8: U7.62(PB8) ; port LCD_CS_OD
PB9: U7.63(PB9) ; port MC_NTC
PB10: U7.30(PB10) ; port MC_CurrentC
PB11: U7.31(PB11)
PB12: U7.32(PB12) ; port MC_EmergencySTOP
PB13: U7.33(PB13)
PB14: U7.34(PB14)
PB15: U7.35(PB15) ; port MC_DissipativeBrake
PC0: U7.13(PC0) ; port EX_RESET_OD
PC1: U7.14(PC1) ; port MC_PFCsync1
PC2: U7.15(PC2) ; port JOY_UP
PC3: U7.16(PC3) ; port JOY_DOWN
PC4: U7.25(PC4) ; port USART1_TX
PC5: U7.26(PC5) ; port USART1_RX
PC6: U7.38(PC6) ; port MC_EnA
PC7: U7.39(PC7) ; port JOY_RIGHT
PC8: U7.48(PC8) ; port JOY_LEFT
PC9: U7.49(PC9) ; port SDcard_detect
PC10: U7.64(PC10) ; port VCP_TX
PC11: U7.1(PC11) ; port VCP_RX
PC12: U7.2(PC12) ; port SPI1_MOSI_DIR
PC13: U7.3(PC13) ; port Tamper_key
PC14: R43.2 U7.4(PC14_-_OSC32_IN)
PC15: R44.2 U7.5(PC15_-_OSC32_OUT)
PD0: U7.50(PD0) ; port MC_PFCsync2
PD1: U7.51(PD1) ; port MicroSD_CS_OD
PD2: U7.52(PD2) ; port MC_UL
PD3: U7.53(PD3) ; port MC_VL
PD4: U7.54(PD4) ; port MC_WL
PD5: U7.55(PD5) ; port LED1
PD6: U7.56(PD6) ; port LED2
PD8: SB11.2 ; port LED3
PD9: SB10.2 ; port LED4
PF0: R45.2 U7.10(PF0_-_OSC_IN)
PF1: R46.2 U7.11(PF1_-_OSC_OUT)
PF2: SB23.2 U7.12(PF2_-_NRST)
PF3: JP15.2 U7.6(PF3_-_VBAT)
PF4: C38.2 SB17.2 SB22.2 TP4.1 U7.7(PF4_-_VREF+)
RESET#: B1.2(B0) B1.3(B1) C88.2 D5.1(A) SB23.1 ; port RESET#
SWCLK: JP9.1 ; port SWCLK
VREF+: SB17.1 ; port VREF+  [a separate net that carries the same name]
NetBT1_1: BT1.1(+) JP15.3
NetC34_1: C34.1 R43.1 X2.2
NetC35_1: C35.1 R44.1 X2.1
NetC36_1: C36.1 R45.1 X3.2(OSC2)
NetC37_1: C37.1 R46.1 X3.1(OSC1)
NetD4_2: D4.2(K) JP9.3
NetD5_2: D5.2(K) JP12.1(COMMON)
NetJP11_2: JP11.2(NO) R84.1
NetR38_1: R38.1 U7.57(PB3)
NetSB10_1: SB10.1 SB13.1 U7.41(PD9[VDD_2])
NetSB11_1: SB11.1 SB14.1 U7.40(PD8[VSS_2])

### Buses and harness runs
bus PA[0..15] = port PA[0..15]
bus PB[0..15] = port PB[0..15]
bus PC[0..15] = port PC[0..15]
bus PD[0..6] = port PD[0..6]
bus PD[8..9] = port PD[8..9]
bus PF[0..4] = port PF[0..4]

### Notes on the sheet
- DB_DET

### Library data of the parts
B1 = SW PUSHBUTTON: SE PUSHBUTTON
BT1 = BATTERY
C31 = Cap Pol1: Polarized Capacitor (Radial); Value: 100pF
C32 C33 C36 C37 = CAP: Capacitor
C34 C35 = Capacitor_ST: as C18 on sheet ST_LINK_V2-1
C38 = Cap: Capacitor
C39 = Cap Pol1: Polarized Capacitor (Radial); Value: 10uF
C88 = CAP: Capacitor; Value: 100pF
D4 D5 = Diode: Default Diode; Code - JEDEC: DO-214-AB
JP9 JP15 = Jumper3
JP11 JP12 = JP2
L1 = Inductor: Value: 100uH
R38 R43-R46 R84 = Res1: Resistor; Value: 1K
SB10 SB11 SB22 SB23 = SB_ON: Fitted: YES; Ordered by: Subcon
SB13 SB14 SB17 = SB_OFF: Fitted: NO; Ordered by: Subcon
TP4 = TP
X2 = CRYSTAL_32K: Crystal
X3 = XTAL: Crystal Oscillator

## Sheet Power.SchDoc: Power
size A4; SheetNumber: 4; SheetTotal: 12
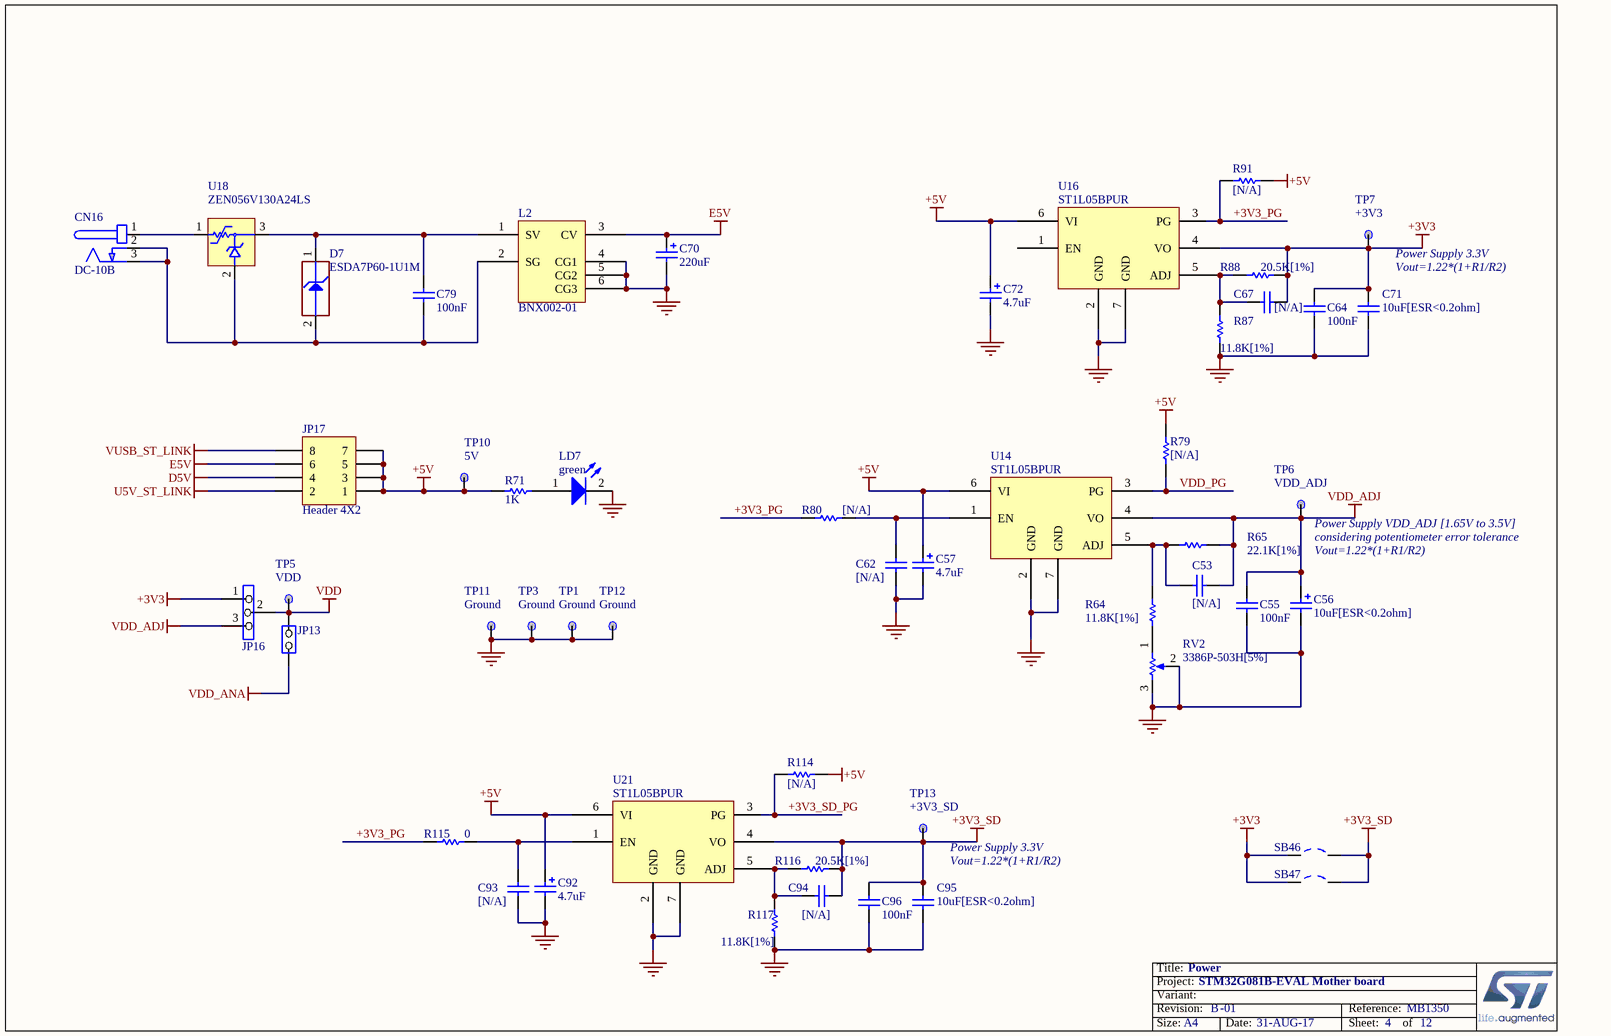
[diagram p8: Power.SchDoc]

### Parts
C53  [N/A]  [0603C]
C55  100nF  [0603C]
C56  10uF[ESR<0.2ohm]  [0805C]
C57  4.7uF  [TAN-A]
C62  [N/A]  [0603C]
C64  100nF  [0603C]
C67  [N/A]  [0603C]
C70  220uF  [c310m-6]
C71  10uF[ESR<0.2ohm]  [0805C]
C72  4.7uF  [TAN-A]
C79  100nF  [0603C]
C92  4.7uF  [TAN-A]
C93  [N/A]  [0603C]
C94  [N/A]  [0603C]
C95  10uF[ESR<0.2ohm]  [0805C]
C96  100nF  [0603C]
CN16  DC-10B  [PWR_JACK_DC10]
D7  ESDA7P60-1U1M  [DO_2SM_1R6X1_21]
JP13  (no value)  [SIP2]
JP16  (no value)  [SIP3]
JP17  Header 4X2  [HDR_2X4_2R54]
L2  BNX002-01  [BNX001]
LD7  green  [0603D]
R64  11.8K[1%]  [0603R]
R65  22.1K[1%]  [0603R]
R71  1K  [0603R]
R79  [N/A]  [0603R]
R80  [N/A]  [0603R]
R87  11.8K[1%]  [0603R]
R88  20.5K[1%]  [0603R]
R91  [N/A]  [0603R]
R114  [N/A]  [0603R]
R115  0  [0603R]
R116  20.5K[1%]  [0603R]
R117  11.8K[1%]  [0603R]
RV2  3386P-503H[5%]  [3386P]
SB46  Solder Bridge OFF  [SB_0603]  (value not drawn)
SB47  Solder Bridge OFF  [SB_0603]  (value not drawn)
TP1  Ground  [TP]
TP3  Ground  [TP]
TP5  VDD  [TP]
TP6  VDD_ADJ  [TP]
TP7  +3V3  [TP]
TP10  5V  [TP]
TP11  Ground  [TP]
TP12  Ground  [TP]
TP13  +3V3_SD  [TP]
U14  ST1L05BPUR  [DFN6_0R95_3X3]
U16  ST1L05BPUR  [DFN6_0R95_3X3]
U18  ZEN056V130A24LS  [TYCO_ZEN056V130A24LS]
U21  ST1L05BPUR  [DFN6_0R95_3X3]

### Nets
+3V3: C64.1 C67.2 C71.1 JP16.1 R88.1 SB46.1 SB47.1 TP7.1 U16.4(VO)
+3V3_SD: C94.2 C95.1 C96.1 R116.1 SB46.2 SB47.2 TP13.1 U21.4(VO)
+5V: C57.1 C72.1 C92.1 JP17.1 JP17.3 JP17.5 JP17.7 R71.2 R79.1 R91.2 R114.2 TP10.1 U14.6(VI) U16.6(VI) U21.6(VI)
D5V: JP17.4
E5V: C70.1 JP17.6 L2.3(CV)
GND: C55.2 C56.2 C57.2 C62.2 C64.2 C70.2 C71.2 C72.2 C92.2 C93.2 C95.2 C96.2 L2.4(CG1) L2.5(CG2) L2.6(CG3) LD7.2(K) R87.2 R117.2 RV2.2(TAP) RV2.3(TOP) TP1.1 TP3.1 TP11.1 TP12.1 U14.2(GND) U14.7(GND) U16.2(GND) U16.7(GND) U21.2(GND) U21.7(GND)
U5V_ST_LINK: JP17.2
VDD: JP13.2(NO) JP16.2 TP5.1
VDD_ADJ: C53.2 C55.1 C56.1 JP16.3 R65.1 TP6.1 U14.4(VO)
VDD_ANA: JP13.1(COMMON)
VUSB_ST_LINK: JP17.8
+3V3_PG: R80.2 R91.1 R115.2 U16.3(PG)
+3V3_SD_PG: R114.1 U21.3(PG)
VDD_PG: R79.2 U14.3(PG)
NetC53_1: C53.1 R64.1 R65.2 U14.5(ADJ)
NetC62_1: C62.1 R80.1 U14.1(EN)
NetC67_1: C67.1 R87.1 R88.2 U16.5(ADJ)
NetC79_1: C79.1 D7.1(IO1) L2.1(SV) U18.3
NetC79_2: C79.2 CN16.2(GND) CN16.3(GND) D7.2(GND) L2.2(SG) U18.2
NetC93_1: C93.1 R115.1 U21.1(EN)
NetC94_1: C94.1 R116.2 R117.1 U21.5(ADJ)
NetCN16_1: CN16.1(+) U18.1
NetLD7_1: LD7.1(A) R71.1
NetR64_2: R64.2 RV2.1(BOT)

Not connected (* = marked no-connect by the designer): U16 1(EN)

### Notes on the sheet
- Power Supply 3.3V
- Vout=1.22*(1+R1/R2)
- (near TP6) Power Supply VDD_ADJ [1.65V to 3.5V]
- (near TP6) considering potentiometer error tolerance

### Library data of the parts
C53 C55 C62 C64 C67 C71 C93-C96 = Cap: Capacitor; Value: 10nF
C56 = Cap Pol1: as C39 on sheet MCU
C57 C72 C92 = Cap Pol1: as C31 on sheet MCU
C70 = Cap Pol1: Polarized Capacitor (Radial); Value: 47uF
C79 = CAP: Capacitor; Value: 100pF
CN16 = PJ202A
D7 = ESDALC6V1-1U2: Dual Transil array for ESD protection; Manuf_1: STM; Ref St: .; ECCN_US/EU: EAR99/NEC; Fitted: YES; Provided: ST
JP13 = JP2
JP16 = Jumper3
JP17 = Header 4X2: Header, 4-Pin, Dual row
L2 = BNX002
LD7 = LED2: as LD5 on sheet ST_LINK_V2-1
R64 R65 R80 R87 R88 R115-R117 = Res1: Resistor; Value: 1K
R71 = res1: Resistor
R79 R91 R114 = res1: Resistor; Value: 1K
RV2 = RV
SB46 SB47 = SB_OFF: Fitted: NO; Ordered by: Subcon
TP1 TP3 TP5-TP7 TP10-TP13 = TP
U14 U16 U21 = ST1L05

## Sheet Motor Control.SchDoc: Motor Control
size A4; SheetNumber: 7; SheetTotal: 12
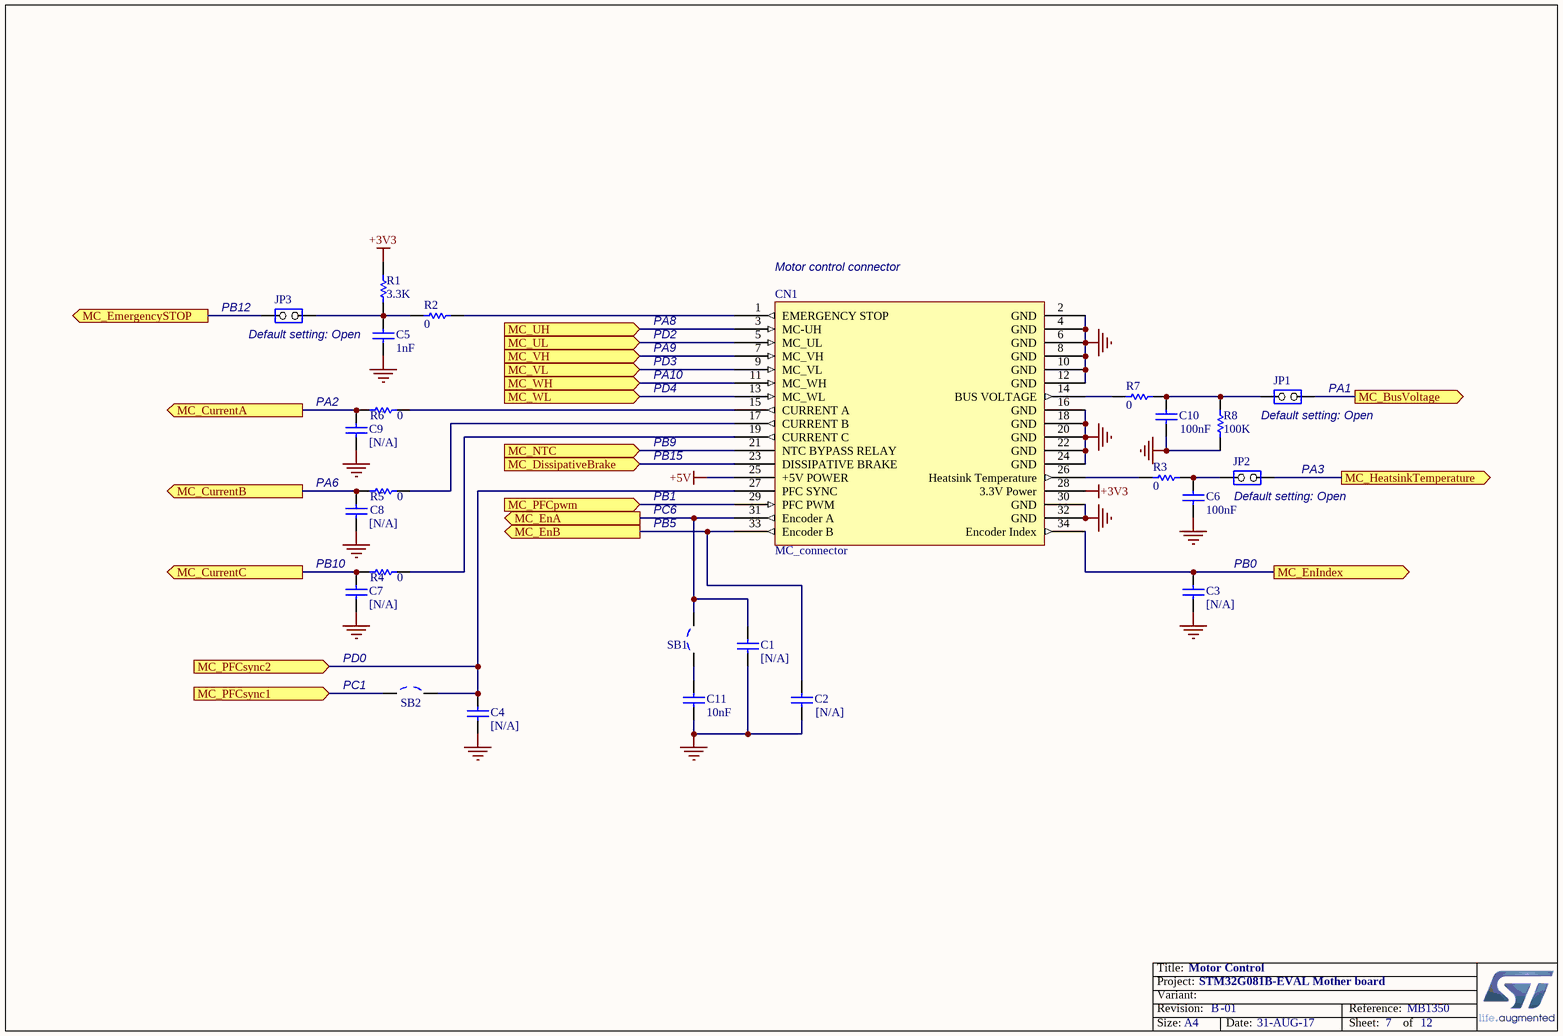
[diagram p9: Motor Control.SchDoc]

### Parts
C1  [N/A]  [0603C]
C2  [N/A]  [0603C]
C3  [N/A]  [0603C]
C4  [N/A]  [0603C]
C5  1nF  [0603C]
C6  100nF  [0603C]
C7  [N/A]  [0603C]
C8  [N/A]  [0603C]
C9  [N/A]  [0603C]
C10  100nF  [0603C]
C11  10nF  [0603C]
CN1  MC_connector  [IDC34S]
JP1  (no value)  [SIP2]
JP2  (no value)  [SIP2]
JP3  (no value)  [SIP2]
R1  3.3K  [0603R]
R2  0  [0603R]
R3  0  [0603R]
R4  0  [0603R]
R5  0  [0603R]
R6  0  [0603R]
R7  0  [0603R]
R8  100K  [0603R]
SB1  Solder Bridge OFF  [SB_0603]  (value not drawn)
SB2  Solder Bridge OFF  [SB_0603]  (value not drawn)

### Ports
MC_BusVoltage (out), MC_CurrentA (out), MC_CurrentB (out), MC_CurrentC (out), MC_DissipativeBrake (in), MC_EmergencySTOP (out), MC_EnA (out), MC_EnB (out), MC_EnIndex (out), MC_HeatsinkTemperature (out), MC_NTC (in), MC_PFCpwm (in), MC_PFCsync1 (in), MC_PFCsync2 (in), MC_UH (in), MC_UL (in), MC_VH (in), MC_VL (in), MC_WH (in), MC_WL (in)

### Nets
+3V3: CN1.28(3.3V_Power) R1.2
+5V: CN1.25(+5V_POWER)
GND: C1.1 C2.1 C3.1 C4.1 C5.1 C6.1 C7.1 C8.1 C9.1 C10.1 C11.1 CN1.2(GND) CN1.4(GND) CN1.6(GND) CN1.8(GND) CN1.10(GND) CN1.12(GND) CN1.16(GND) CN1.18(GND) CN1.20(GND) CN1.22(GND) CN1.24(GND) CN1.30(GND) CN1.32(GND) R8.1
PA1: JP1.1(COMMON) ; port MC_BusVoltage
PA2: C9.2 R6.1 ; port MC_CurrentA
PA3: JP2.1(COMMON) ; port MC_HeatsinkTemperature
PA6: C8.2 R5.1 ; port MC_CurrentB
PA8: CN1.3(MC-UH) ; port MC_UH
PA9: CN1.7(MC_VH) ; port MC_VH
PA10: CN1.11(MC_WH) ; port MC_WH
PB0: C3.2 CN1.34(Encoder_Index) ; port MC_EnIndex
PB1: CN1.29(PFC_PWM) ; port MC_PFCpwm
PB5: C2.2 CN1.33(Encoder_B) ; port MC_EnB
PB9: CN1.21(NTC_BYPASS_RELAY) ; port MC_NTC
PB10: C7.2 R4.1 ; port MC_CurrentC
PB12: JP3.2(NO) ; port MC_EmergencySTOP
PB15: CN1.23(DISSIPATIVE_BRAKE) ; port MC_DissipativeBrake
PC1: SB2.1 ; port MC_PFCsync1
PC6: C1.2 CN1.31(Encoder_A) SB1.2 ; port MC_EnA
PD0: C4.2 CN1.27(PFC_SYNC) SB2.2 ; port MC_PFCsync2
PD2: CN1.5(MC_UL) ; port MC_UL
PD3: CN1.9(MC_VL) ; port MC_VL
PD4: CN1.13(MC_WL) ; port MC_WL
NetC5_2: C5.2 JP3.1(COMMON) R1.1 R2.2
NetC6_2: C6.2 JP2.2(NO) R3.2
NetC10_2: C10.2 JP1.2(NO) R7.2 R8.2
NetC11_2: C11.2 SB1.1
NetCN1_1: CN1.1(EMERGENCY_STOP) R2.1
NetCN1_14: CN1.14(BUS_VOLTAGE) R7.1
NetCN1_15: CN1.15(CURRENT_A) R6.2
NetCN1_17: CN1.17(CURRENT_B) R5.2
NetCN1_19: CN1.19(CURRENT_C) R4.2
NetCN1_26: CN1.26(Heatsink_Temperature) R3.1

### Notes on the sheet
- (near JP3) PB12
- (near CN1) Motor control connector
- Default setting: Open
- PA8
- PD2
- PA9
- PD3
- PA10
- PA2
- PD4
- PB9
- (near JP1) Default setting: Open
- (near JP1) PA1
- PA6
- PB15
- PB1
- PC6
- (near JP2) Default setting: Open
- PA3
- PB10
- PB5
- PB0
- (near SB2) PC1
- PD0

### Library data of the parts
C1-C4 C6-C11 = cap: Capacitor; Value: 100pF
C5 = CAP: Capacitor; Value: 100pF
JP1-JP3 = JP2
R1-R8 = Res1: Resistor; Value: 1K
SB1 SB2 = SB_OFF: Fitted: NO; Ordered by: Subcon

## Sheet Extension connectors.SchDoc: Extension connectors
size A4; SheetNumber: 10; SheetTotal: 12
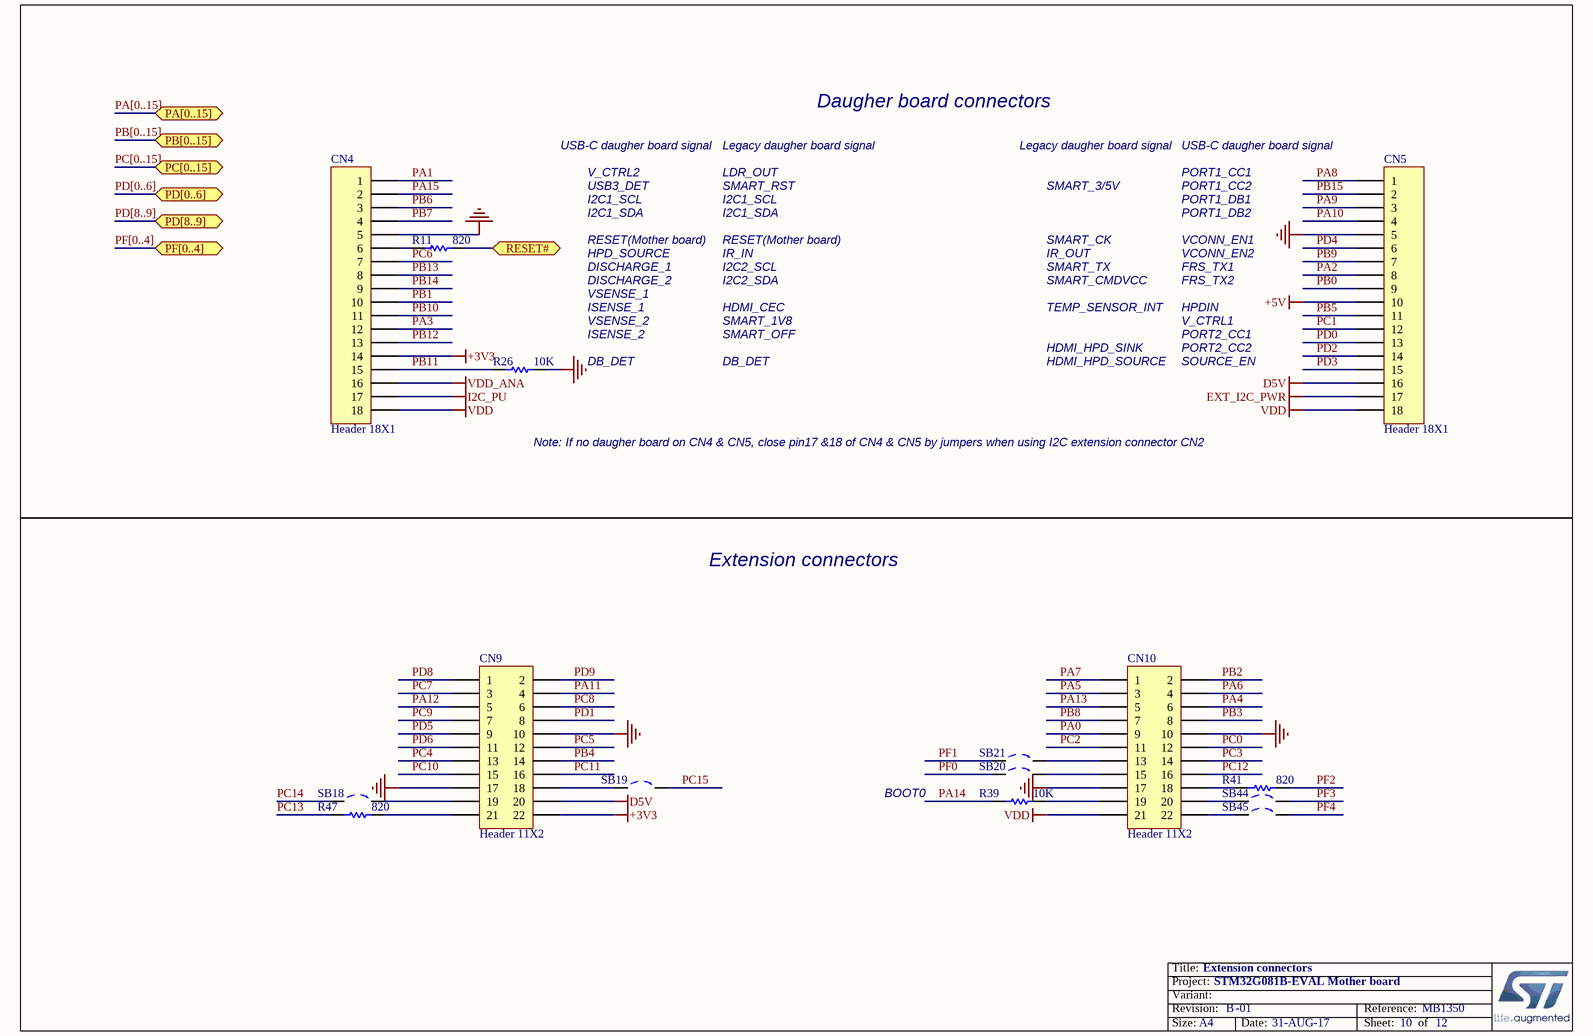
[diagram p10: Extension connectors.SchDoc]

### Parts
CN4  Header 18X1  [HDR_1X18_2R54]
CN5  Header 18X1  [HDR_1X18_2R54]
CN9  Header 11X2  [HDR_2X11_2R54]
CN10  Header 11X2  [HDR_2X11_2R54]
R11  820  [0603R]
R26  10K  [0603R]
R39  10K  [0603R]
R41  820  [0603R]
R47  820  [0603R]
SB18  Solder Bridge OFF  [SB_0603]  (value not drawn)
SB19  Solder Bridge OFF  [SB_0603]  (value not drawn)
SB20  Solder Bridge OFF  [SB_0603]  (value not drawn)
SB21  Solder Bridge OFF  [SB_0603]  (value not drawn)
SB44  Solder Bridge OFF  [SB_0603]  (value not drawn)
SB45  Solder Bridge OFF  [SB_0603]  (value not drawn)

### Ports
PA[0..15] (bidir), PB[0..15] (bidir), PC[0..15] (bidir), PD[0..6] (bidir), PD[8..9] (bidir), PF[0..4] (bidir), RESET# (bidir)

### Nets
+3V3: CN4.14 CN9.22
+5V: CN5.10
D5V: CN5.16 CN9.20
EXT_I2C_PWR: CN5.17
GND: CN4.5 CN5.5 CN9.10 CN9.17 CN10.10 CN10.17 R26.1
I2C_PU: CN4.17
VDD: CN4.18 CN5.18 CN10.21
VDD_ANA: CN4.16
PA0: CN10.9
PA1: CN4.1
PA2: CN5.8
PA3: CN4.12
PA4: CN10.6
PA5: CN10.3
PA6: CN10.4
PA7: CN10.1
PA8: CN5.1
PA9: CN5.3
PA10: CN5.4
PA11: CN9.4
PA12: CN9.5
PA13: CN10.5
PA14: R39.2
PA15: CN4.2
PB0: CN5.9
PB1: CN4.10
PB2: CN10.2
PB3: CN10.8
PB4: CN9.14
PB5: CN5.11
PB6: CN4.3
PB7: CN4.4
PB8: CN10.7
PB9: CN5.7
PB10: CN4.11
PB11: CN4.15 R26.2
PB12: CN4.13
PB13: CN4.8
PB14: CN4.9
PB15: CN5.2
PC0: CN10.12
PC1: CN5.12
PC2: CN10.11
PC3: CN10.14
PC4: CN9.13
PC5: CN9.12
PC6: CN4.7
PC7: CN9.3
PC8: CN9.6
PC9: CN9.7
PC10: CN9.15
PC11: CN9.16
PC12: CN10.16
PC13: R47.2
PC14: SB18.1
PC15: SB19.2
PD0: CN5.13
PD1: CN9.8
PD2: CN5.14
PD3: CN5.15
PD4: CN5.6
PD5: CN9.9
PD6: CN9.11
PD8: CN9.1
PD9: CN9.2
PF0: SB20.1
PF1: SB21.1
PF2: R41.1
PF3: SB44.2
PF4: SB45.2
RESET#: R11.1 ; port RESET#
NetCN4_6: CN4.6 R11.2
NetCN9_18: CN9.18 SB19.1
NetCN9_19: CN9.19 SB18.2
NetCN9_21: CN9.21 R47.1
NetCN10_13: CN10.13 SB21.2
NetCN10_15: CN10.15 SB20.2
NetCN10_18: CN10.18 R41.2
NetCN10_19: CN10.19 R39.1
NetCN10_20: CN10.20 SB44.1
NetCN10_22: CN10.22 SB45.1

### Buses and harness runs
bus PA[0..15] = port PA[0..15]
bus PB[0..15] = port PB[0..15]
bus PC[0..15] = port PC[0..15]
bus PD[0..6] = port PD[0..6]
bus PD[8..9] = port PD[8..9]
bus PF[0..4] = port PF[0..4]

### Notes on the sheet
- Daugher board connectors
- USB-C daugher board signal
- V_CTRL2
- Legacy daugher board signal
- LDR_OUT
- PORT1_CC1
- (near CN5) USB-C daugher board signal
- USB3_DET
- I2C1_SCL
- I2C1_SDA
- RESET(Mother board)
- SMART_RST
- SMART_CK
- SMART_3/5V
- PORT1_DB1
- VCONN_EN1
- PORT1_CC2
- PORT1_DB2
- DISCHARGE_1
- DISCHARGE_2
- VSENSE_1
- ISENSE_1
- HPD_SOURCE
- IR_IN
- I2C2_SCL
- I2C2_SDA
- HDMI_CEC
- IR_OUT
- SMART_TX
- TEMP_SENSOR_INT
- SMART_CMDVCC
- HPDIN
- VCONN_EN2
- FRS_TX1
- FRS_TX2
- DB_DET
- ISENSE_2
- VSENSE_2
- SMART_OFF
- SMART_1V8
- HDMI_HPD_SINK
- HDMI_HPD_SOURCE
- SOURCE_EN
- V_CTRL1
- PORT2_CC1
- PORT2_CC2
- Note: If no daugher board on CN4 & CN5, close pin17 &18 of CN4 & CN5 by jumpers when using I2C extension connector CN2
- Extension connectors
- BOOT0

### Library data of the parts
CN4 CN5 = Header 18X1: Header, 20-Pin, Single row
CN9 CN10 = Header 11X2: Header, 11-Pin, Dual row
R11 R41 R47 = Res1: Resistor; Value: 1K
R26 R39 = res1: Resistor; Value: 1K
SB18-SB21 SB44 SB45 = SB_OFF: Fitted: NO; Ordered by: Subcon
